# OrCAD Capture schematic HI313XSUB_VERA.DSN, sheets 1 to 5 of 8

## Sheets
1 PAGE1_Title Page
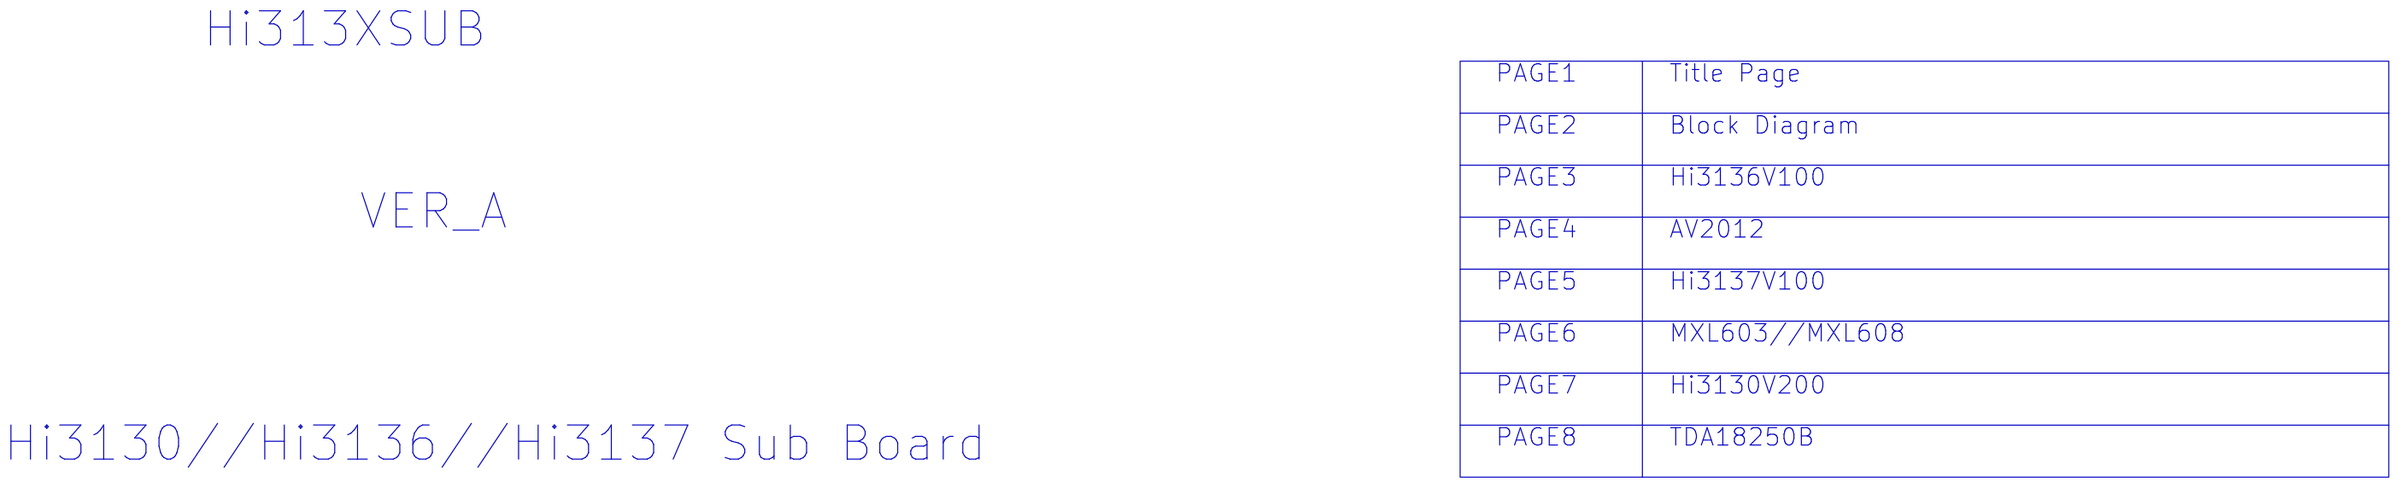
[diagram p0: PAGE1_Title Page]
2 PAGE2_Block Diagram: size Custom
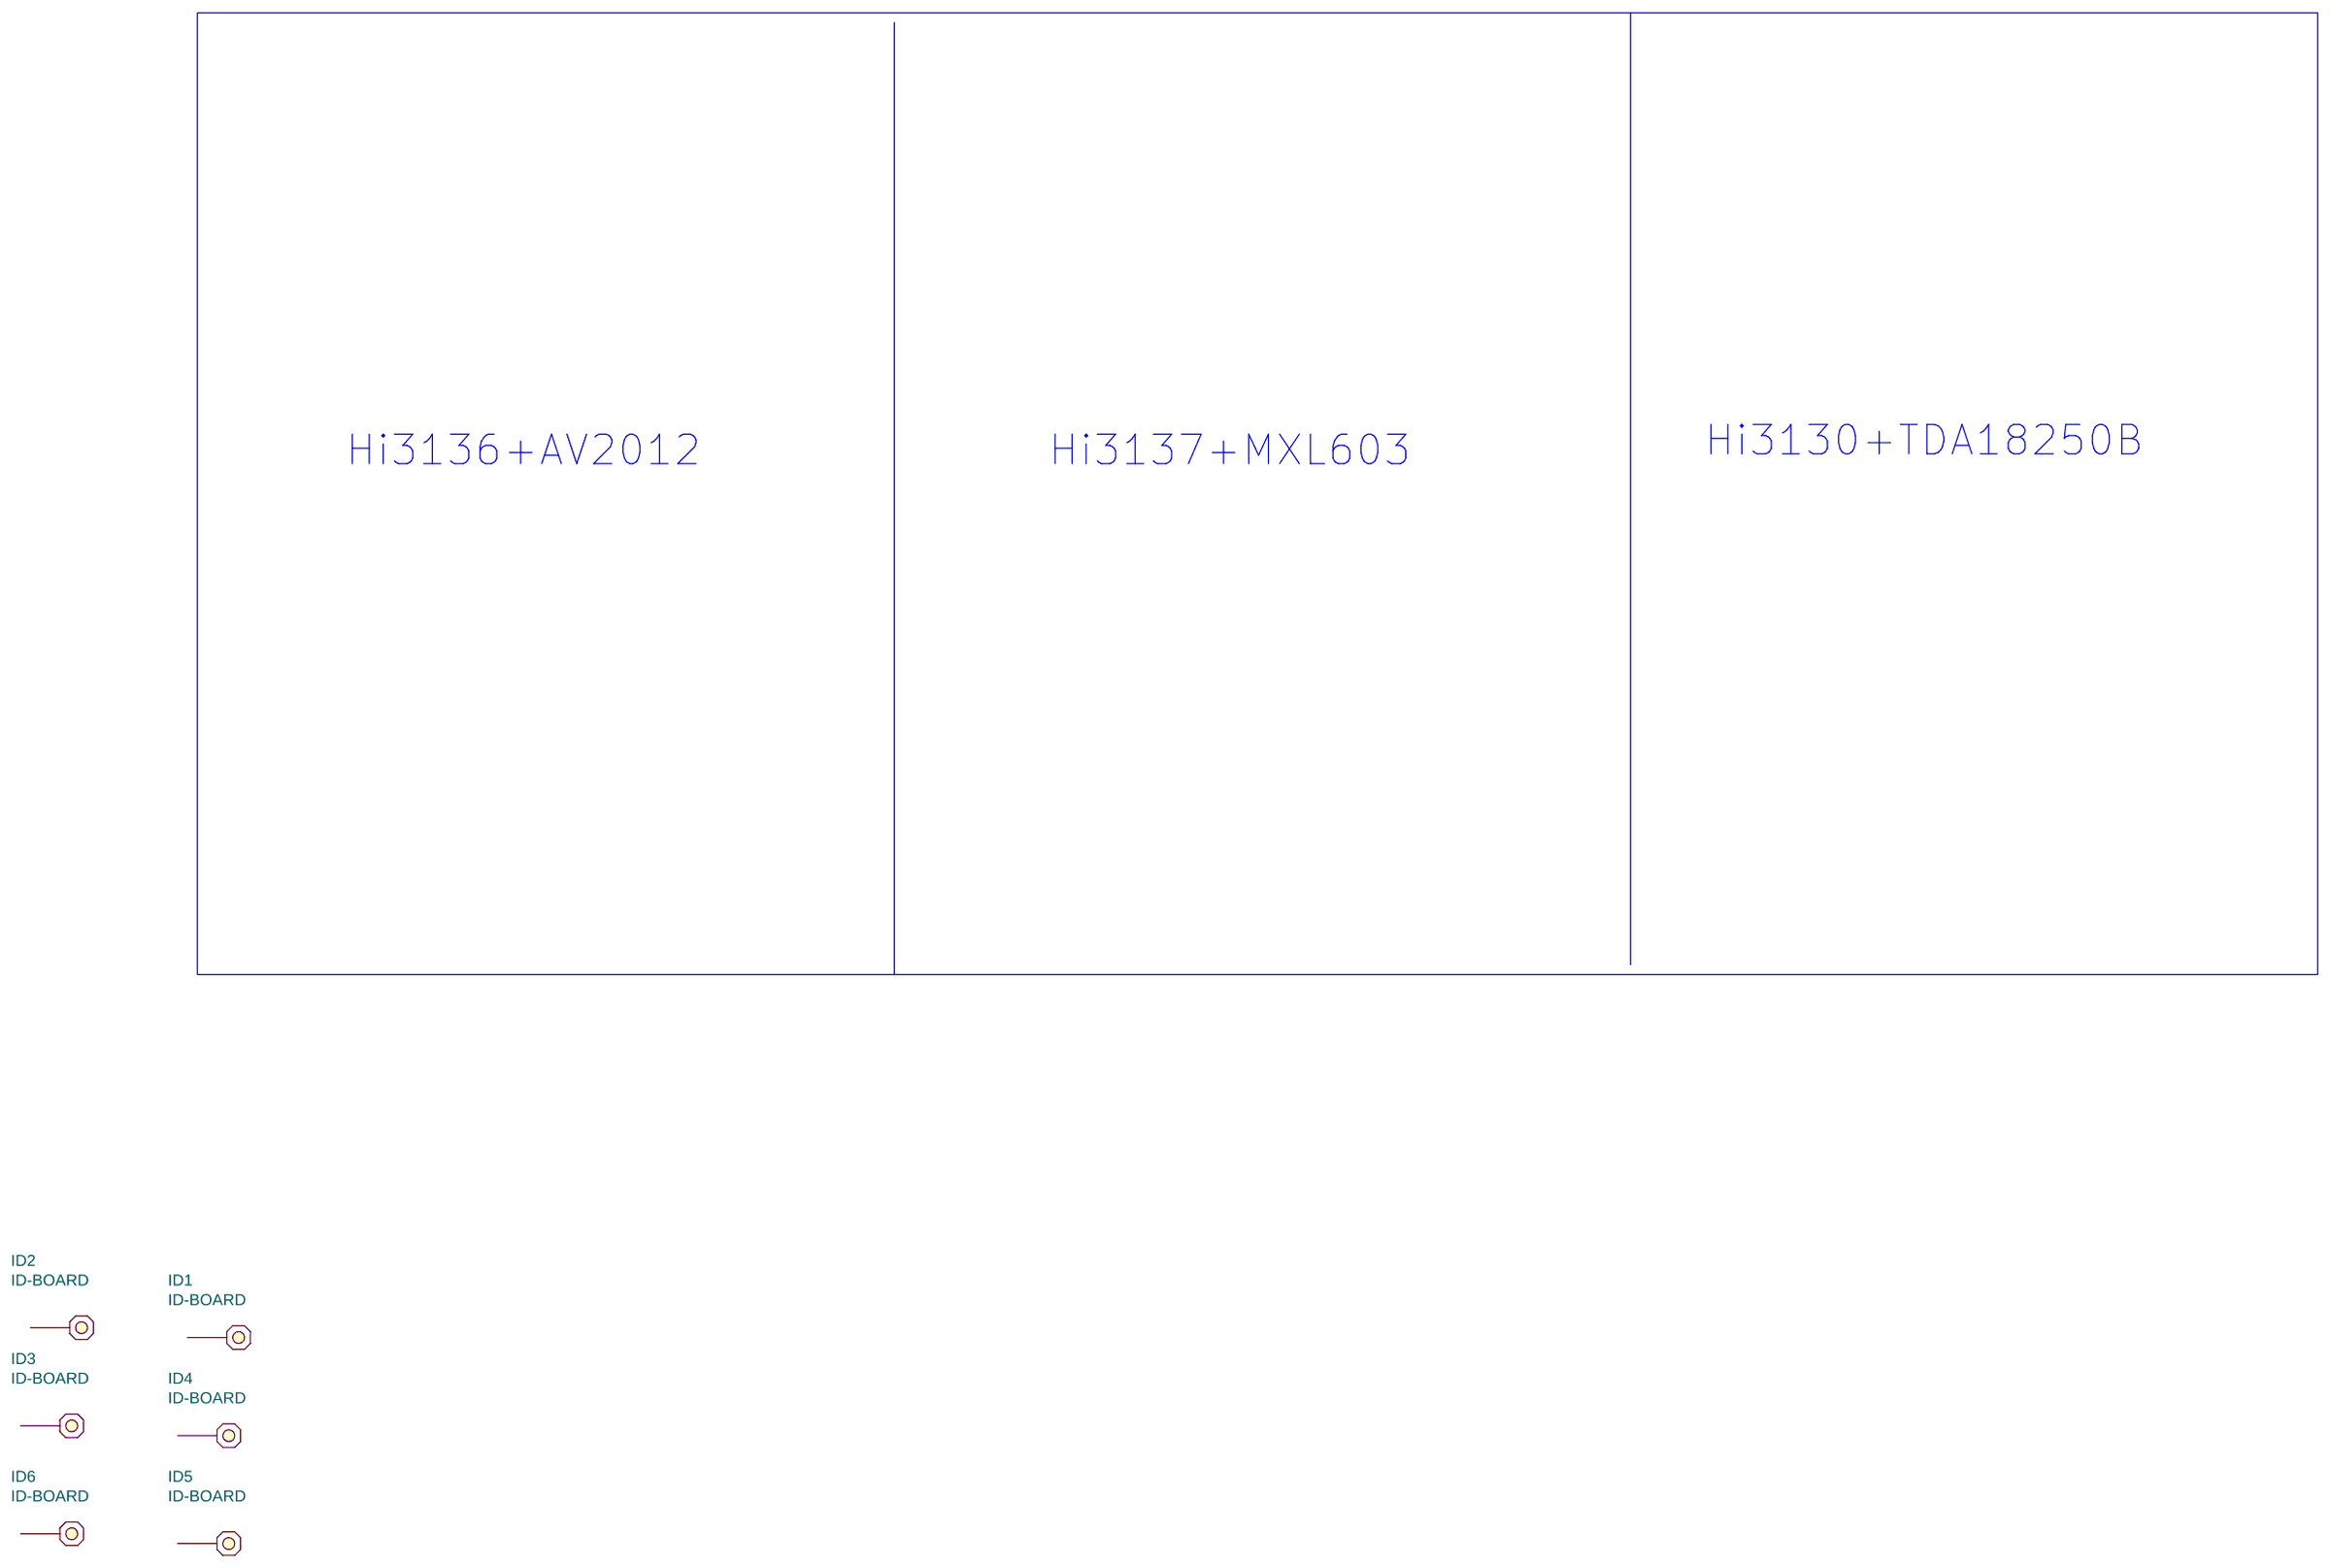
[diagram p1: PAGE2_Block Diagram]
3 PAGE3_Hi3136V100: size Custom
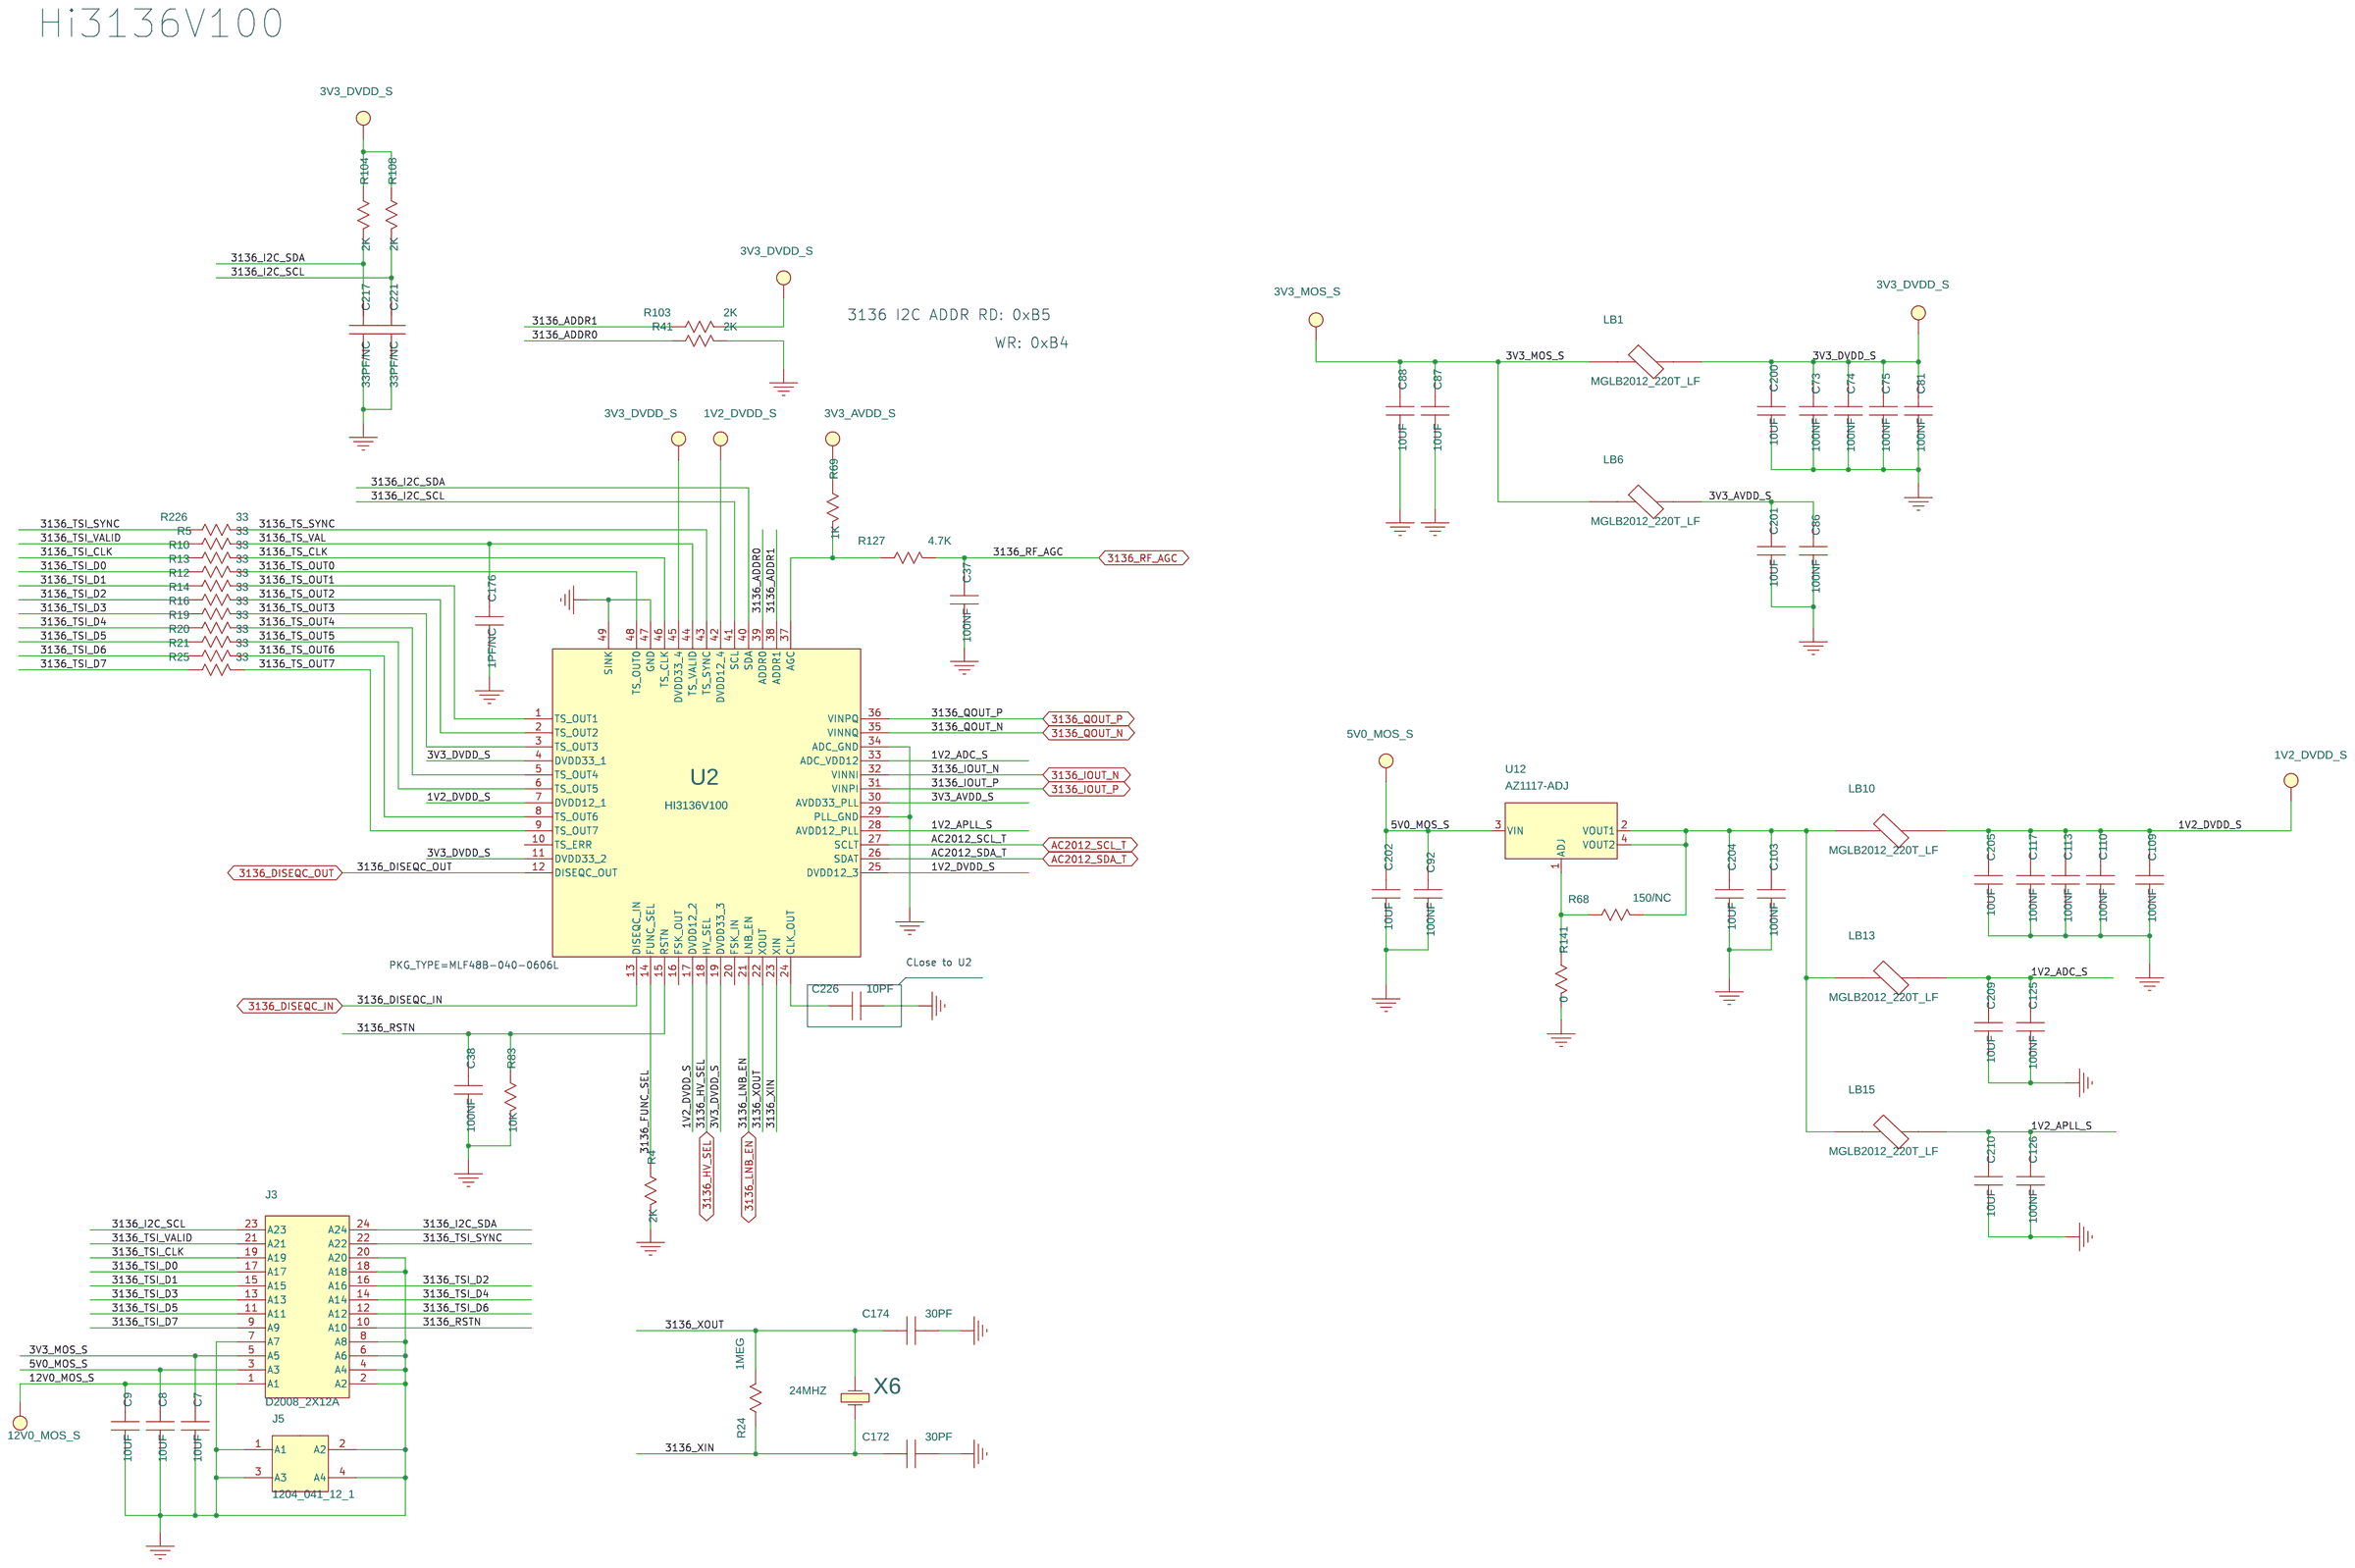
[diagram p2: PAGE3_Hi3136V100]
4 PAGE4_AV2012: size Custom
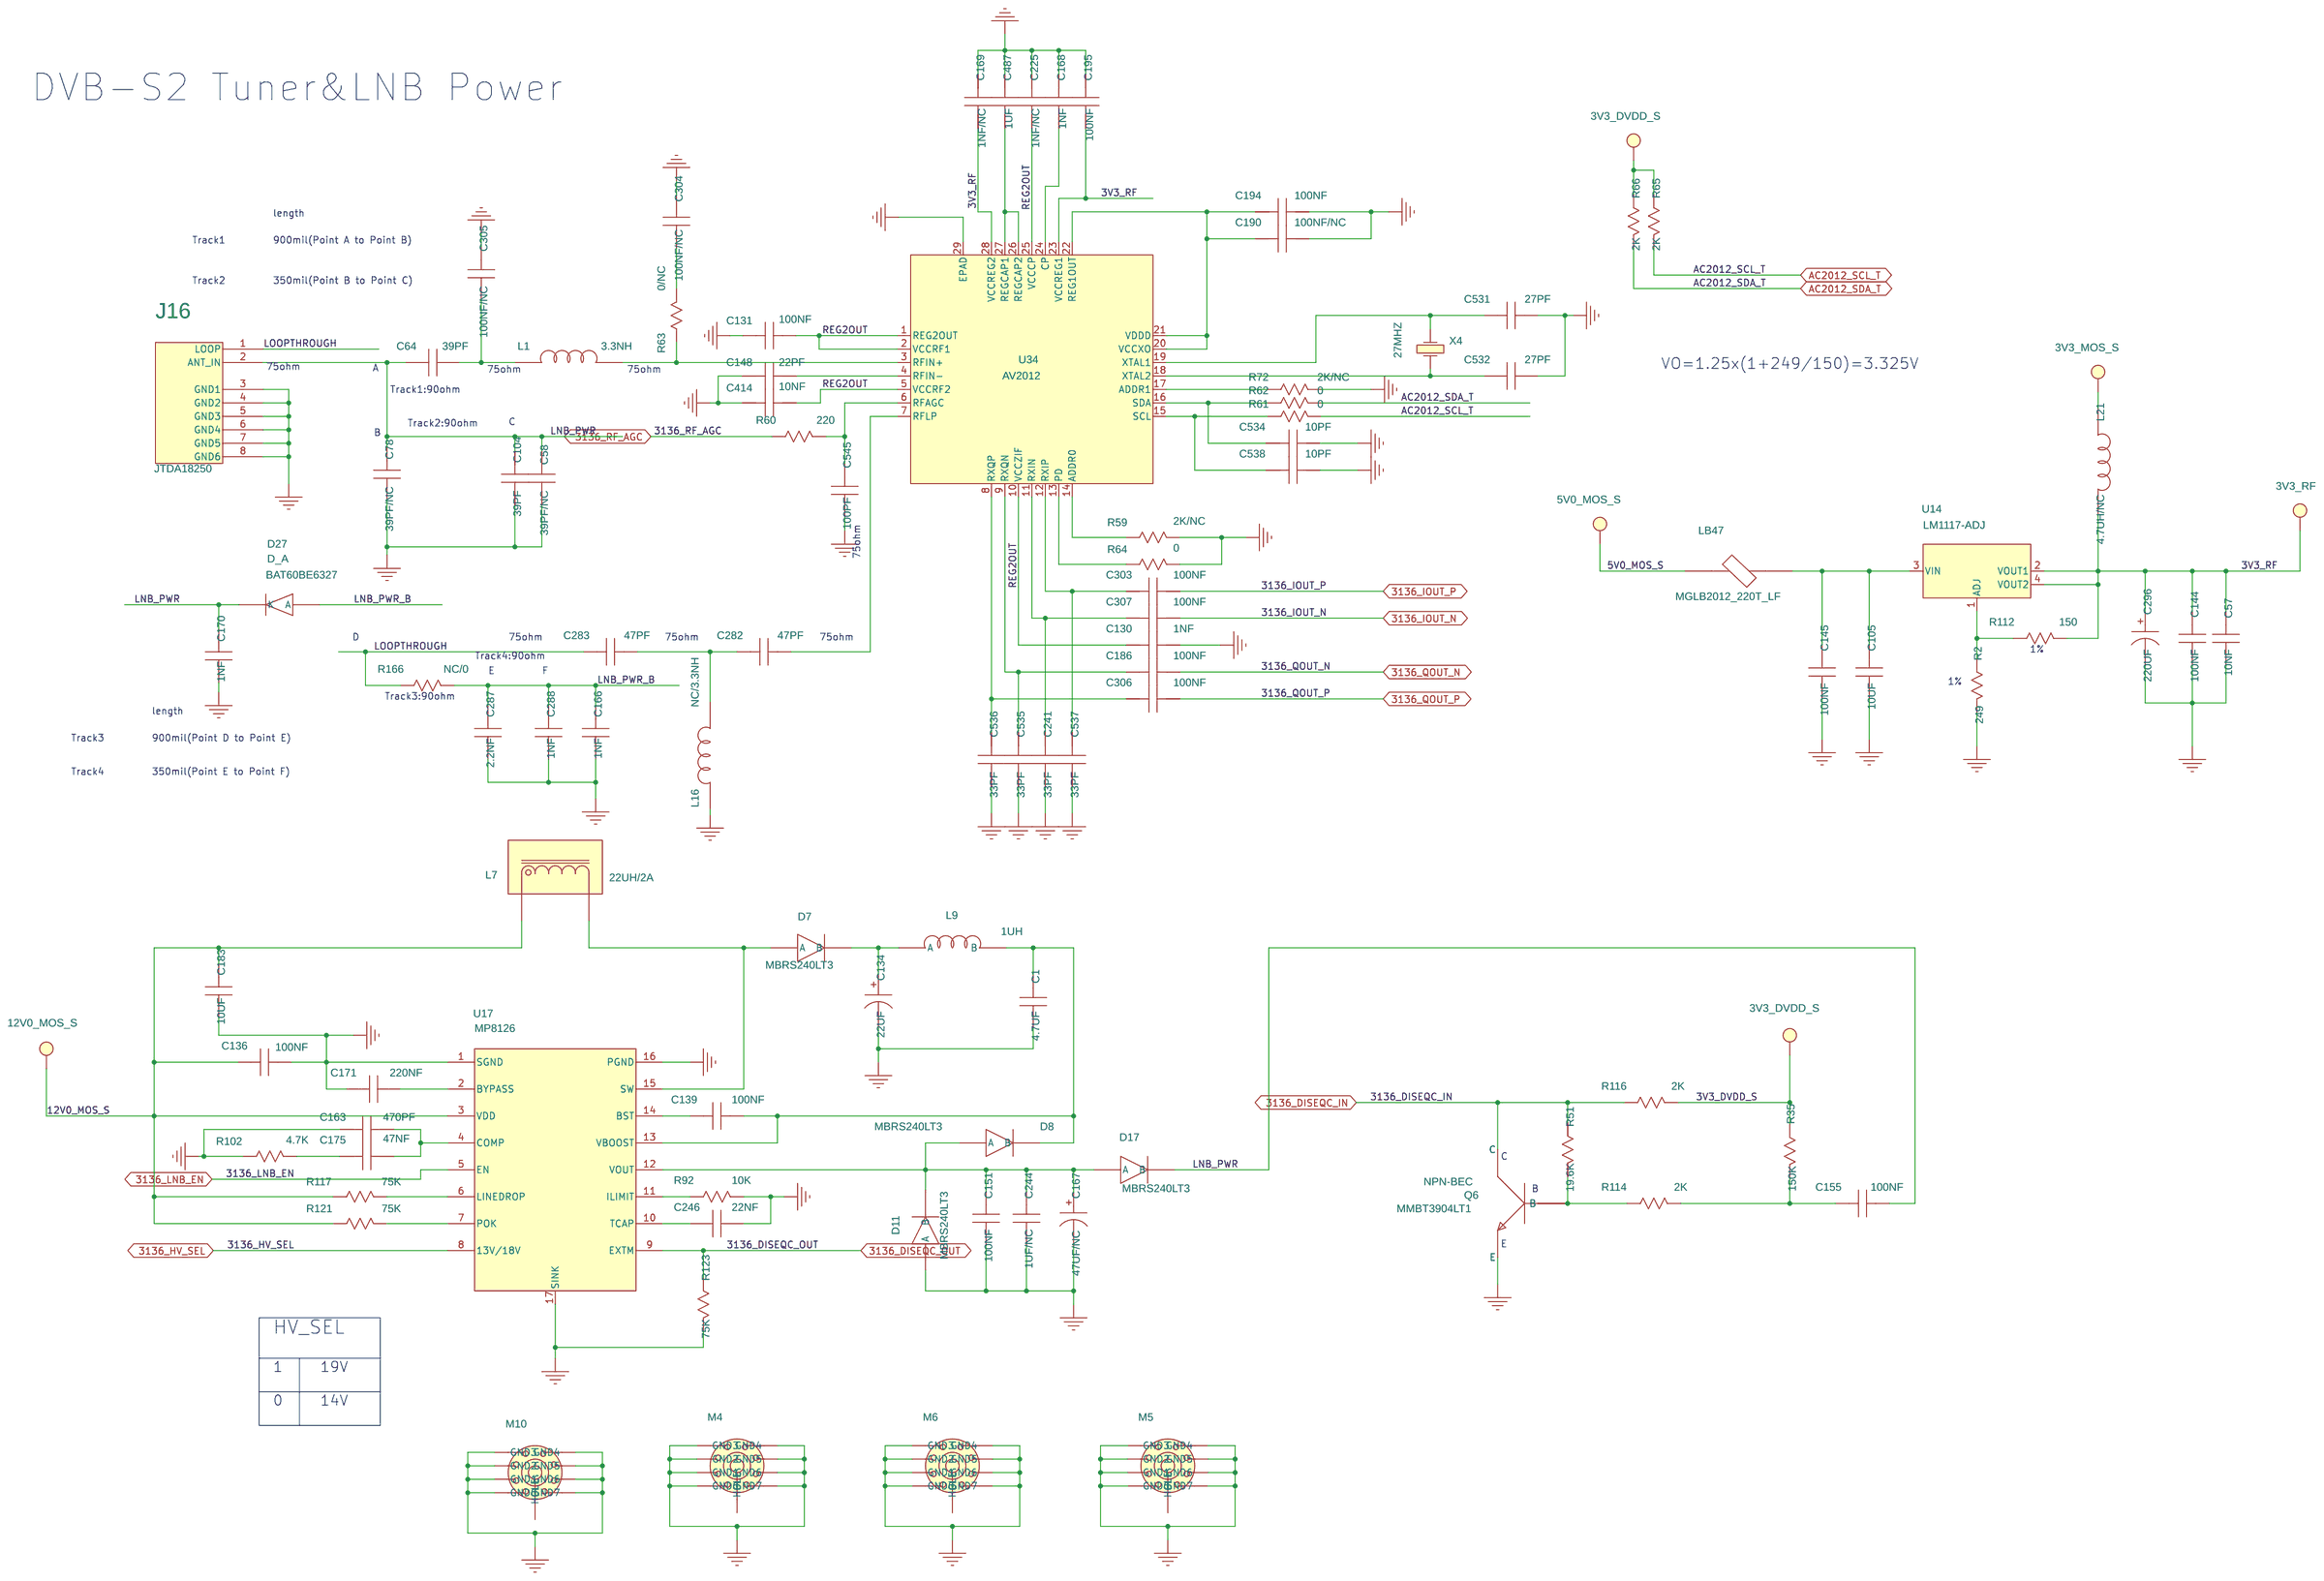
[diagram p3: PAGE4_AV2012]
5 PAGE5_Hi3137V100: size Custom
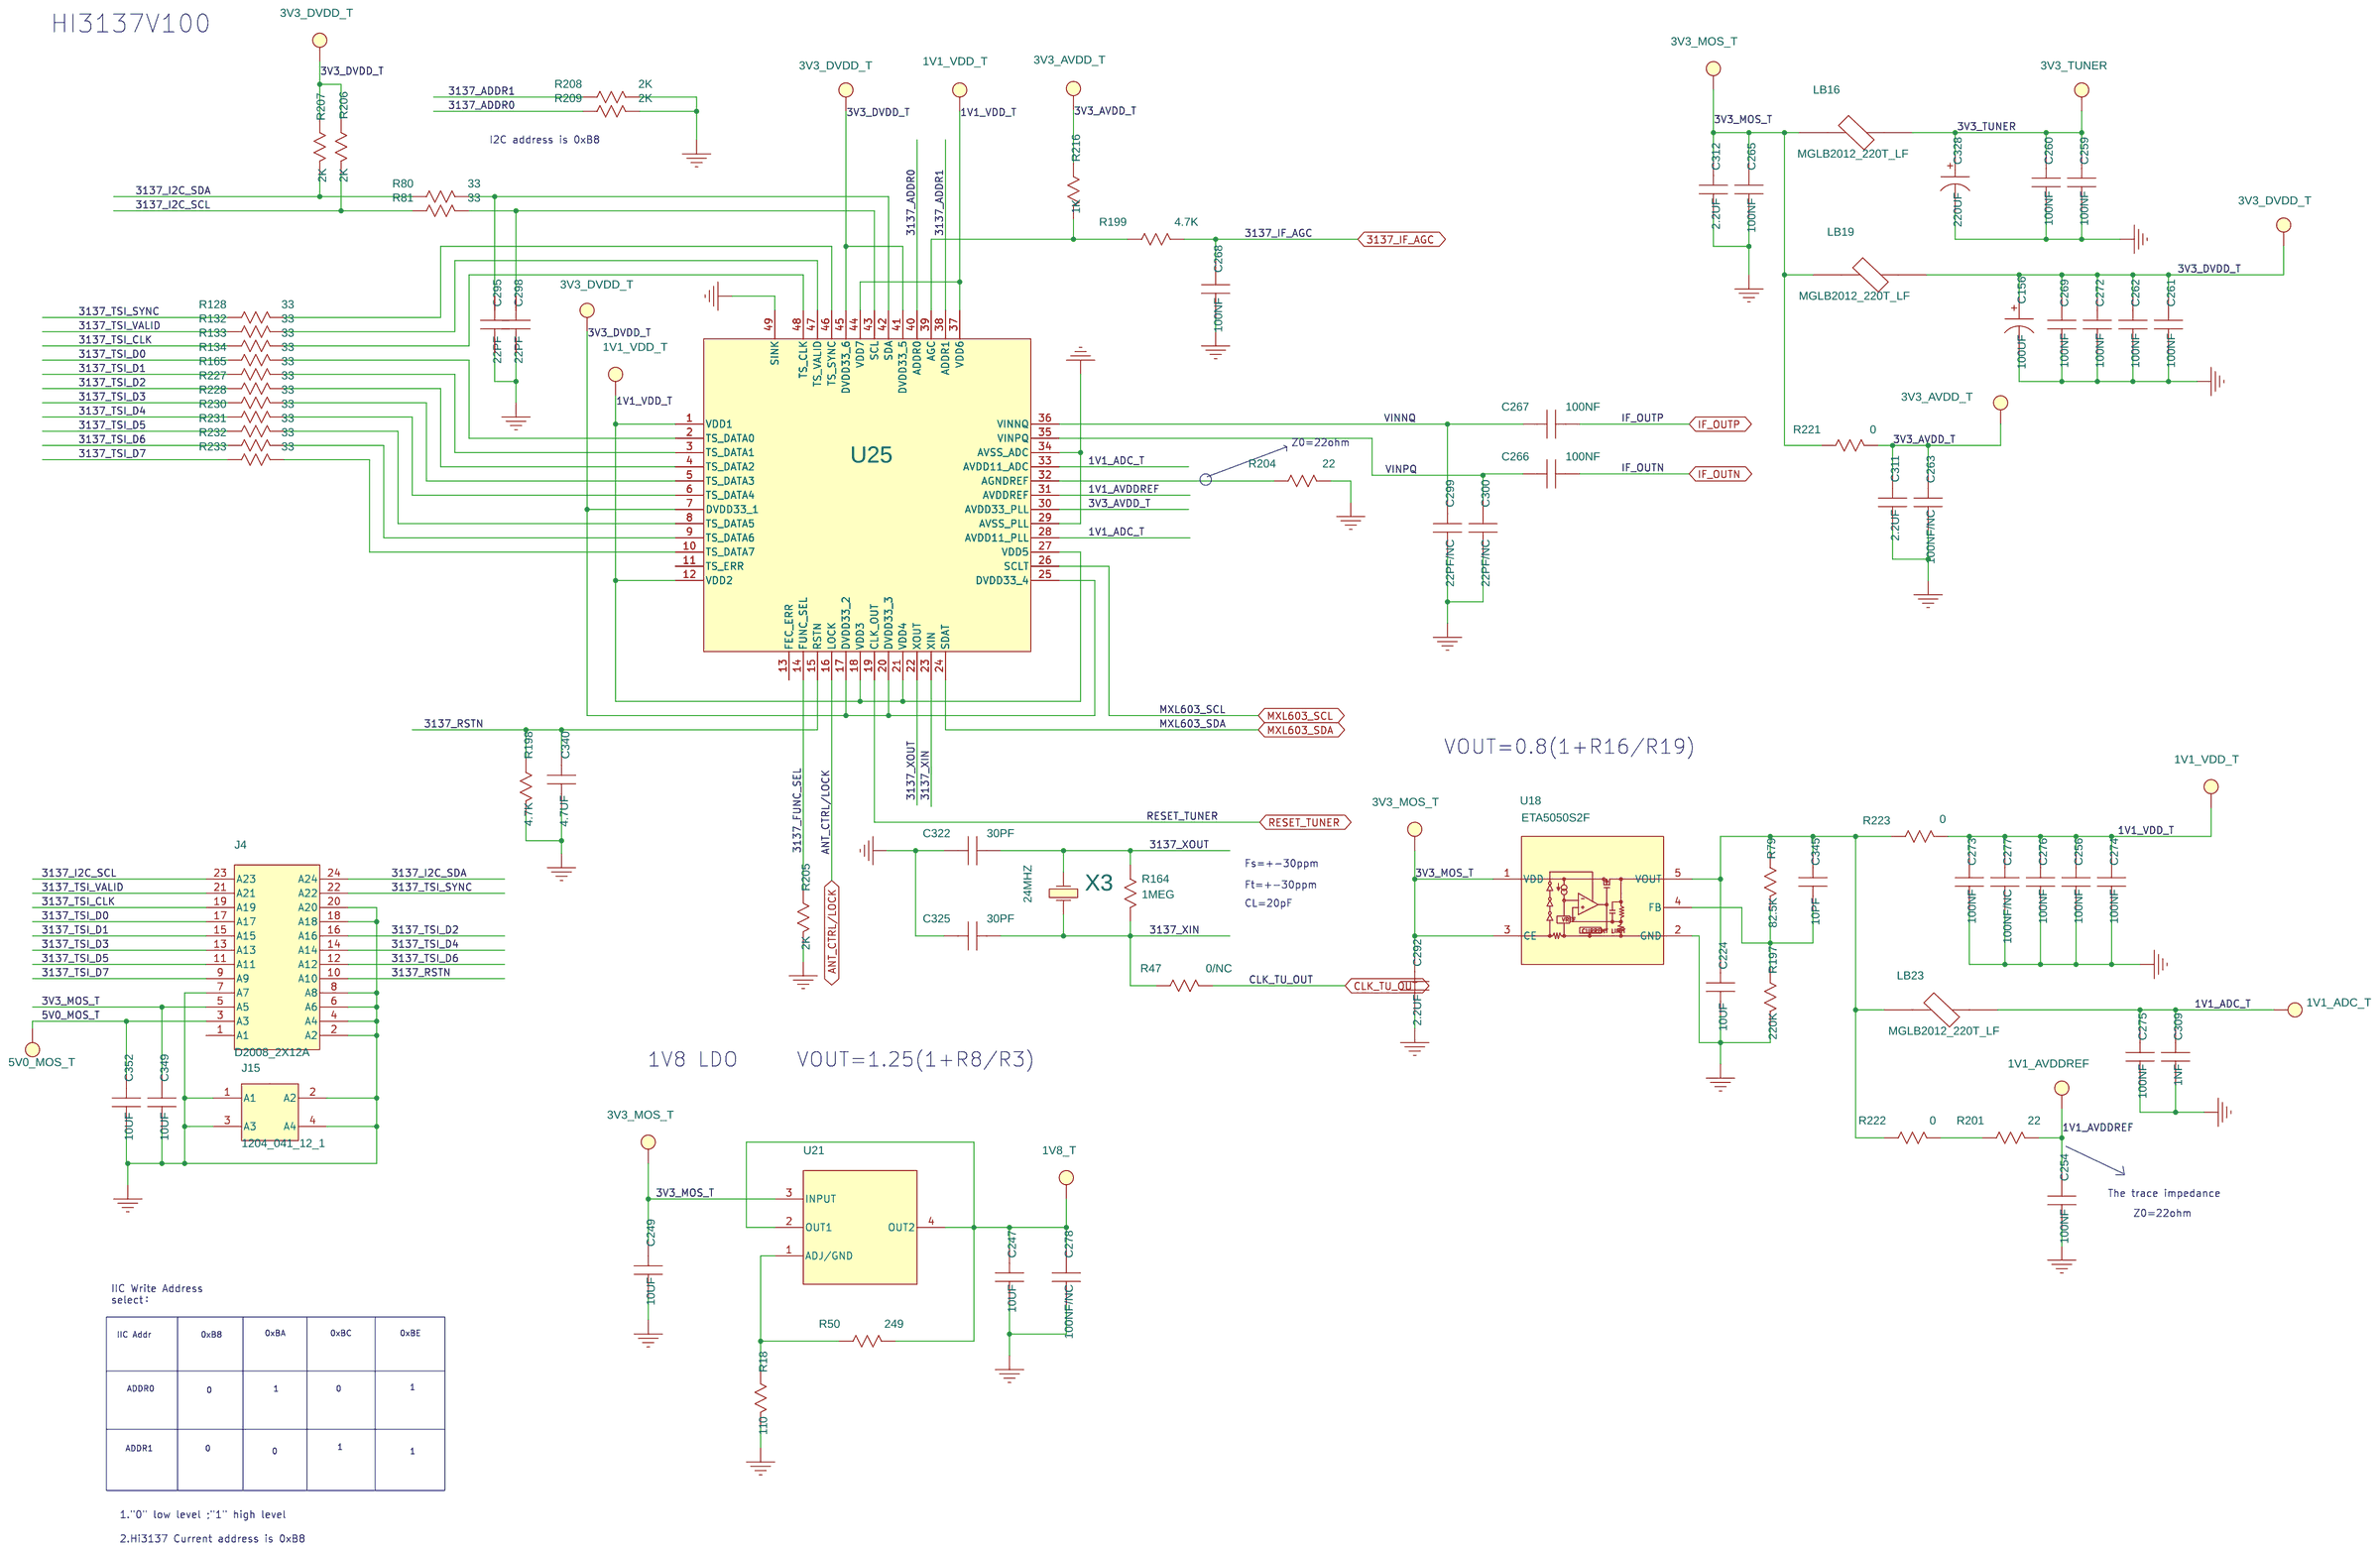
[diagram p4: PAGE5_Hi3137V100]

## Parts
sheet PAGE2_Block Diagram
ID1  ID-BOARD  [ID-BOARD]
ID2  ID-BOARD  [ID-BOARD]
ID3  ID-BOARD  [ID-BOARD]
ID4  ID-BOARD  [ID-BOARD]
ID5  ID-BOARD  [ID-BOARD]
ID6  ID-BOARD  [ID-BOARD]
sheet PAGE3_Hi3136V100
C7  10UF  [SC0603]
C8  10UF  [SC0805]
C9  10UF  [SC0805]
C37  100NF  [SC0402]
C38  100NF  [SC0402]
C73  100NF  [SC0402]
C74  100NF  [SC0402]
C75  100NF  [SC0402]
C81  100NF  [SC0402]
C86  100NF  [SC0402]
C87  10UF  [SC0603]
C88  10UF  [SC0603]
C92  100NF  [SC0402]
C103  100NF  [SC0402]
C109  100NF  [SC0402]
C110  100NF  [SC0402]
C113  100NF  [SC0402]
C117  100NF  [SC0402]
C125  100NF  [SC0402]
C126  100NF  [SC0402]
C172  30PF  [SC0402]
C174  30PF  [SC0402]
C176  1PF/NC  [SC0402]
C200  10UF  [SC0603]
C201  10UF  [SC0603]
C202  10UF  [SC0603]
C204  10UF  [SC0603]
C205  10UF  [SC0603]
C209  10UF  [SC0603]
C210  10UF  [SC0603]
C217  33PF/NC  [SC0402]
C221  33PF/NC  [SC0402]
C226  10PF  [SC0402]
J3  WBC2X12  [HEAD0212-RM-SUB]
J5  HEAD2X2  [HEAD0202-RM]
LB1  LB  [SL0805]
LB6  LB  [SL0805]
LB10  LB  [SL0805]
LB13  LB  [SL0805]
LB15  LB  [SL0805]
R4  2K  [SR0402]
R5  33  [SR0402]
R10  33  [SR0402]
R12  33  [SR0402]
R13  33  [SR0402]
R14  33  [SR0402]
R16  33  [SR0402]
R19  33  [SR0402]
R20  33  [SR0402]
R21  33  [SR0402]
R24  1MEG  [SR0402]
R25  33  [SR0402]
R41  2K  [SR0402]
R68  150/NC  [SR0402]
R69  1K  [SR0402]
R83  10K  [SR0402]
R103  2K  [SR0402]
R104  2K  [SR0402]
R108  2K  [SR0402]
R127  4.7K  [SR0402]
R141  0  [SR0603]
R226  33  [SR0402]
U2  HI3136V100  [MLF48B-040-0606L]
U12  AZ1117-ADJ  [TO-252]
X6  24MHZ  [SX2-1205]
sheet PAGE4_AV2012
C1  4.7UF  [SC1210]
C57  10NF  [HSC0402]
C58  39PF/NC  [SC0402]
C64  39PF  [SC0402]
C78  39PF/NC  [SC0402]
C104  39PF  [SC0402]
C105  10UF  [SC1206]
C130  1NF  [SC0402]
C131  100NF  [SC0402]
C134  22UF  [CAPC2-100-200]
C136  100NF  [SC0402]
C139  100NF  [SC0402]
C144  100NF  [SC0402]
C145  100NF  [SC0402]
C148  22PF  [SC0402]
C151  100NF  [SC0402]
C155  100NF  [SC0402]
C163  470PF  [SC0402]
C166  1NF  [SC0402]
C167  47UF/NC  [SCAPC2-0606]
C168  1NF  [SC0603]
C169  1NF/NC  [SC0603]
C170  1NF  [SC0402]
C171  220NF  [SC0805]
C175  47NF  [SC0402]
C183  10UF  [SC1206]
C186  100NF  [SC0402]
C190  100NF/NC  [SC0402]
C194  100NF  [SC0402]
C195  100NF  [SC0402]
C225  1NF/NC  [SC0603]
C241  33PF  [SC0402]
C244  1UF/NC  [SC1206]
C246  22NF  [SC0603]
C282  47PF  [SC0402]
C283  47PF  [SC0402]
C287  2.2NF  [SC0402]
C288  1NF  [SC0402]
C296  220UF  [CAPC2-100-250]
C303  100NF  [SC0402]
C304  100NF/NC  [SC0402]
C305  100NF/NC  [SC0402]
C306  100NF  [SC0402]
C307  100NF  [SC0402]
C414  10NF  [SC0402]
C487  1UF  [SC0603]
C531  27PF  [SC0402]
C532  27PF  [SC0402]
C534  10PF  [SC0402]
C535  33PF  [SC0402]
C536  33PF  [SC0402]
C537  33PF  [SC0402]
C538  10PF  [SC0402]
C545  100PF  [SC0402]
D7  DIODE  [SD1714A]
D8  DIODE  [SD1714A]
D11  DIODE  [SD1714A]
D17  DIODE  [SD1714A]
D27  D_A  [HSOD323A]
J16  JTDA18250  [JTDA18250]
L1  3.3NH  [SL0402]
L7  22UH/2A  [L6X6X4_5]
L9  1UH  [SWPA4020S]
L16  NC/3.3NH  [SL0402]
L21  4.7UH/NC  [HSL1007]
LB47  LB  [SL0805]
M4  HOLE-8STARS  [HOLE138-8STAR]
M5  HOLE-8STARS  [HOLE138-8STAR]
M6  HOLE-8STARS  [HOLE138-8STAR]
M10  HOLE-8STARS  [HOLE138-8STAR]
Q6  NPN-BEC  [SOT23]
R2  249  [SR0603]
R35  150K  [SR0603]
R51  19.6K  [SR0603]
R59  2K/NC  [SR0402]
R60  220  [SR0402]
R61  0  [SR0402]
R62  0  [SR0402]
R63  0/NC  [SR0402]
R64  0  [SR0402]
R65  2K  [SR0402]
R66  2K  [SR0402]
R72  2K/NC  [SR0402]
R92  10K  [SR0402]
R102  4.7K  [SR0402]
R112  150  [SR0402]
R114  2K  [SR0603]
R116  2K  [SR0603]
R117  75K  [SR0402]
R121  75K  [SR0402]
R123  75K  [SR0402]
R166  NC/0  [SR0402]
U14  LM1117-ADJ  [SOT223A]
U17  MP8126  [TSSOP16EP]
U34  AV2012  [QFN28B-040-0404LH]
X4  27MHZ  [SX2-1205]
sheet PAGE5_Hi3137V100
C156  100UF  [CAPC2-79-217]
C224  10UF  [SC0805]
C247  10UF  [SC0805]
C249  10UF  [SC0805]
C254  100NF  [SC0402]
C256  100NF  [SC0402]
C259  100NF  [SC0402]
C260  100NF  [SC0402]
C261  100NF  [SC0402]
C262  100NF  [SC0402]
C263  100NF/NC  [SC0402]
C265  100NF  [SC0402]
C266  100NF  [SC0402]
C267  100NF  [SC0402]
C268  100NF  [SC0402]
C269  100NF  [SC0402]
C272  100NF  [SC0402]
C273  100NF  [SC0402]
C274  100NF  [SC0402]
C275  100NF  [SC0402]
C276  100NF  [SC0402]
C277  100NF/NC  [SC0402]
C278  100NF/NC  [SC0402]
C292  2.2UF  [SC0603]
C295  22PF  [SC0402]
C298  22PF  [SC0402]
C299  22PF/NC  [SC0402]
C300  22PF/NC  [SC0402]
C309  1NF  [SC0402]
C311  2.2UF  [SC0805]
C312  2.2UF  [SC0805]
C322  30PF  [SC0402]
C325  30PF  [SC0402]
C328  220UF  [CAPC2-100-250]
C340  4.7UF  [SC0603]
C345  10PF  [SC0402]
C349  10UF  [SC0805]
C352  10UF  [SC0805]
J4  WBC2X12  [HEAD0212-RM-SUB]
J15  HEAD2X2  [HEAD0202-RM]
LB16  LB  [SL0805]
LB19  LB  [SL0805]
LB23  LB  [SL0805]
R18  110  [SR0603]
R47  0/NC  [SR0402]
R50  249  [SR0603]
R79  82.5K  [SR0603]
R80  33  [SR0402]
R81  33  [SR0402]
R128  33  [SR0402]
R132  33  [SR0402]
R133  33  [SR0402]
R134  33  [SR0402]
R164  1MEG  [SR0402]
R165  33  [SR0402]
R197  220K  [SR0603]
R198  4.7K  [SR0603]
R199  4.7K  [SR0603]
R201  22  [SR0402]
R204  22  [SR0402]
R205  2K  [SR0402]
R206  2K  [SR0402]
R207  2K  [SR0402]
R208  2K  [SR0402]
R209  2K  [SR0402]
R216  1K  [SR0603]
R221  0  [SR0603]
R222  0  [SR0603]
R223  0  [SR0603]
R227  33  [SR0402]
R228  33  [SR0402]
R230  33  [SR0402]
R231  33  [SR0402]
R232  33  [SR0402]
R233  33  [SR0402]
U18  ETA5050  [SOT23-5]
U21  TLV1117CKTPR  [SOT223A]
U25  HI3137V100  [MLF48G-040-0606L]
X3  24MHZ  [SX2-1205]

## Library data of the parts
ID1-ID6 = ID-BOARD
C7 C87 C88 C200-C202 C204 C205 C209 C210 = C: %182%%238%%182%%168%%185%%164%%215%%247%%181%%231%%209%%185%(V): 6.3; %195%%232%%202%%246%: SMD陶瓷电容-6.3V-10000NF-+/-20%-X5R-0603-BT,TS16949; %208%%161%%192%%224%%195%%251%%179%%198%: SMD陶瓷电容; CODE: 8070649; COMPONENT_HIGH_MAX: 0.9MM; DEVICE: C1608X5R0J106MT0A0E
C8 C9 C349 C352 = C: %182%%238%%182%%168%%185%%164%%215%%247%%181%%231%%209%%185%(V): 25; %195%%232%%202%%246%: SMD陶瓷电容-25V-10000NF-+/-20%-X5R-0805; %208%%161%%192%%224%%195%%251%%179%%198%: SMD陶瓷电容; CODE: 8071629; COMPONENT_HIGH_MAX: 1.45MM; DEVICE: C2012X5R1E106KT000N1
C37 C38 C136 C139 C144 C145 C151 C155 C265 = C: %182%%238%%182%%168%%185%%164%%215%%247%%181%%231%%209%%185%(V): 16; %195%%232%%202%%246%: SMD陶瓷电容-16V-100NF-+/-10%-X7R-0402-BT; %208%%161%%192%%224%%195%%251%%179%%198%: SMD陶瓷电容; CODE: 8070614; COMPONENT_HIGH_MAX: 0.6MM; DEVICE: RMEMK105BJ104KV_FR
C73-C75 C81 C86 C92 C103 C109 C110 C113 C117 C125 C126 = C: %182%%238%%182%%168%%185%%164%%215%%247%%181%%231%%209%%185%(V): 10; %195%%232%%202%%246%: SMD陶瓷电容-10V-100NF-+/-10%-X5R-0402; %208%%161%%192%%224%%195%%251%%179%%198%: SMD陶瓷电容; CODE: 8070561; COMPONENT_HIGH_MAX: 0.55MM; DEVICE: C0402C104K8PAC_7867
C172 C174 C322 C325 = C: %182%%238%%182%%168%%185%%164%%215%%247%%181%%231%%209%%185%(V): 50; %195%%232%%202%%246%: SMD陶瓷电容-50V-0.03NF-+/-5%-NPO-0402; %208%%161%%192%%224%%195%%251%%179%%198%: SMD陶瓷电容; CODE: 8070604; COMPONENT_HIGH_MAX: 0.55MM; DEVICE: GRM1555C1H300J
C176 = C: %182%%238%%182%%168%%185%%164%%215%%247%%181%%231%%209%%185%(V): 50; %195%%232%%202%%246%: SMD陶瓷电容-50V-0.001NF-+/-0.1PF-NPO-0402-BT; %208%%161%%192%%224%%195%%251%%179%%198%: SMD陶瓷电容; CODE: 8070578; COMPONENT_HIGH_MAX: 0.55MM; DEVICE: GRM1555C1H1R0B
C217 C221 C241 C535-C537 = C: %182%%238%%182%%168%%185%%164%%215%%247%%181%%231%%209%%185%(V): 50; %195%%232%%202%%246%: SMD陶瓷电容-50V-0.033NF-+/-5%-NP0-0402-BT; %208%%161%%192%%224%%195%%251%%179%%198%: SMD陶瓷电容; CODE: 8070547; COMPONENT_HIGH_MAX: 0.55MM; DEVICE: CC0402JRNPO9BN330
C226 C345 = C: %182%%238%%182%%168%%185%%164%%215%%247%%181%%231%%209%%185%(V): 50; %195%%232%%202%%246%: SMD陶瓷电容-50V-0.01NF-+/-5%-NP0-0402-BT; %208%%161%%192%%224%%195%%251%%179%%198%: SMD陶瓷电容; CODE: 8070530; COMPONENT_HIGH_MAX: 0.56MM; DEVICE: 04025A100JAT2A
J3 J4 = WBC2X12: %195%%232%%202%%246%: 华为文档 00383947 - 得康（D2008－2×12A） A; CODE: 383947; COMPONENT_HIGH_MAX: 6.7MM; DEVICE: D2008_2X12A
J5 J15 = HEAD2X2: %195%%232%%202%%246%: 插针-普通方脚插针-4PIN-双排-弯脚-5.84MM-3.18MM-2.54MM-THT; %208%%161%%192%%224%%195%%251%%179%%198%: 插针; CODE: 14050061; COMPONENT_HIGH_MAX: 5.2MM; DEVICE: 1204_041_12_1
LB1 LB6 LB10 LB13 LB15 LB23 = LB: %195%%232%%202%%246%: EMI磁珠-+/-25%-220OHM-0.05OHM-2A-0805; %208%%161%%192%%224%%195%%251%%179%%198%: EMI磁珠; CODE: 10070012; COMPONENT_HIGH_MAX: 1.05MM; DEVICE: MGLB2012_220T_LF
R4 R41 R59 R72 R103 R104 R108 R205-R209 = R: %182%%238%%182%%168%%185%%166%%194%%202%(W): 0.06; %195%%232%%202%%246%: 片式厚膜电阻器-0.0625W-2000OHM-+/-1%-0402-BT; %208%%161%%192%%224%%195%%251%%179%%198%: 片式厚膜电阻器; %215%%232%%214%%181%%212%%202%%208%%237%%198%%171%%178%%238%: +/-1%; CODE: 7091354; COMPONENT_HIGH_MAX: 0.4MM; DEVICE: RC_02W2001FT
R5 R10 R12-R14 R16 R19-R21 R25 R80 R81 R128 R132-R134 R165 R226-R228 R230-R233 = R: %182%%238%%182%%168%%185%%166%%194%%202%(W): 0.06; %195%%232%%202%%246%: 片式厚膜电阻器-0.0625W-33OHM-+/-1%-0402; %208%%161%%192%%224%%195%%251%%179%%198%: 片式厚膜电阻器; %215%%232%%214%%181%%212%%202%%208%%237%%198%%171%%178%%238%: +/-1%; CODE: 7090836; COMPONENT_HIGH_MAX: 0.4MM; DEVICE: RC0402FR_0733RL
R24 R164 = R: %182%%238%%182%%168%%185%%166%%194%%202%(W): 0.06; %195%%232%%202%%246%: 片式厚膜电阻器-0.0625W-1000000OHM-+/-1%-0402; %208%%161%%192%%224%%195%%251%%179%%198%: 片式厚膜电阻器; %215%%232%%214%%181%%212%%202%%208%%237%%198%%171%%178%%238%: +/-1%; CODE: 7090857; COMPONENT_HIGH_MAX: 0.4MM; DEVICE: RK73H1ETTP1004F
R68 = R: %182%%238%%182%%168%%185%%166%%194%%202%(W): 0.06; %195%%232%%202%%246%: 片式厚膜电阻器-0.0625W-150OHM-+/-5%-0402; %208%%161%%192%%224%%195%%251%%179%%198%: 片式厚膜电阻器; %215%%232%%214%%181%%212%%202%%208%%237%%198%%171%%178%%238%: +/-5%; CODE: 7090788; COMPONENT_HIGH_MAX: 0.4MM; DEVICE: RK73B1ELTP151J
R69 = R: %182%%238%%182%%168%%185%%166%%194%%202%(W): 0.06; %195%%232%%202%%246%: 片式厚膜电阻器-0.0625W-1000OHM-+/-5%-0402-BT; %208%%161%%192%%224%%195%%251%%179%%198%: 片式厚膜电阻器; %215%%232%%214%%181%%212%%202%%208%%237%%198%%171%%178%%238%: +/-5%; CODE: 7090809; COMPONENT_HIGH_MAX: 0.4MM; DEVICE: RC0402JR_071KL
R83 = R: %182%%238%%182%%168%%185%%166%%194%%202%(W): 0.06; %195%%232%%202%%246%: 片式厚膜电阻器-0.0625W-10000OHM-+/-5%-0402-BT; %208%%161%%192%%224%%195%%251%%179%%198%: 片式厚膜电阻器; %215%%232%%214%%181%%212%%202%%208%%237%%198%%171%%178%%238%: +/-5%; CODE: 7090815; COMPONENT_HIGH_MAX: 0.4MM; DEVICE: RC_02W103JT
R102 R127 = R: %182%%238%%182%%168%%185%%166%%194%%202%(W): 0.06; %195%%232%%202%%246%: 片式厚膜电阻器-0.0625W-4700OHM-+/-5%-0402-BT; %208%%161%%192%%224%%195%%251%%179%%198%: 片式厚膜电阻器; %215%%232%%214%%181%%212%%202%%208%%237%%198%%171%%178%%238%: +/-5%; CODE: 7090793; COMPONENT_HIGH_MAX: 0.4MM; DEVICE: RK73B1ELTP472J
R141 R221-R223 = R: %182%%238%%182%%168%%185%%166%%194%%202%(W): 0.1; %195%%232%%202%%246%: 片式厚膜电阻器-0.1W-0OHM-<50MOHM-0603-1A-BT,TS16949; %208%%161%%192%%224%%195%%251%%179%%198%: 片式厚膜电阻器; %215%%232%%214%%181%%212%%202%%208%%237%%198%%171%%178%%238%: <50MOHM; CODE: 7090522; COMPONENT_HIGH_MAX: 0.6MM; DEVICE: RC0603JR_070RL
U2 = HI3136V100
U12 = AZ1117-ADJ_0
X3 X6 = X3: %195%%232%%202%%246%: 晶体谐振器-24MHZ-20PF-+/-30PPM-40OHM-HC-49S; %208%%161%%192%%224%%195%%251%%179%%198%: 晶体谐振器; CODE: 12020090; COMPONENT_HIGH_MAX: 4.2MM; DEVICE: ESB240000F20D33
C1 = C: %182%%238%%182%%168%%185%%164%%215%%247%%181%%231%%209%%185%(V): 50; %195%%232%%202%%246%: SMD陶瓷电容-50V-4700NF-+/-20%-X7R-1210; %208%%161%%192%%224%%195%%251%%179%%198%: SMD陶瓷电容; CODE: 8070690; COMPONENT_HIGH_MAX: 2.8MM; DEVICE: C3225X7R1H475MT000E
C57 = C: %182%%238%%182%%168%%185%%164%%215%%247%%181%%231%%209%%185%(V): 50; %195%%232%%202%%246%: SMD陶瓷电容-50V-10NF-10%-X7R-0402-终端专用; %208%%161%%192%%224%%195%%251%%179%%198%: SMD陶瓷电容; CODE: 8070970; COMPONENT_HIGH_MAX: 0.55MM; DEVICE: 0402B103K500CT
C58 C64 C78 C104 = C: %182%%238%%182%%168%%185%%164%%215%%247%%181%%231%%209%%185%(V): 50; %195%%232%%202%%246%: SMD陶瓷电容-50V-0.039NF-+/-5%-NPO-0402; %208%%161%%192%%224%%195%%251%%179%%198%: SMD陶瓷电容; CODE: 8070605; COMPONENT_HIGH_MAX: 0.55MM; DEVICE: GRM1555C1H390JZ01D
C105 = C: %182%%238%%182%%168%%185%%164%%215%%247%%181%%231%%209%%185%(V): 10; %195%%232%%202%%246%: SMD陶瓷电容-10V-10000NF-+/-10% -X7R-1206; %208%%161%%192%%224%%195%%251%%179%%198%: SMD陶瓷电容; CODE: 8070729; COMPONENT_HIGH_MAX: 1.8MM; DEVICE: 1206B106K100CT
C130 C309 = C: %182%%238%%182%%168%%185%%164%%215%%247%%181%%231%%209%%185%(V): 50; %195%%232%%202%%246%: SMD陶瓷电容-50V-1NF-+/-10%-X7R-0402-BT; %208%%161%%192%%224%%195%%251%%179%%198%: SMD陶瓷电容; CODE: 8070531; COMPONENT_HIGH_MAX: 0.56MM; DEVICE: 04025C102KAT2A
C131 C186 C190 C194 C195 C303-C307 = C: %182%%238%%182%%168%%185%%164%%215%%247%%181%%231%%209%%185%(V): 10; %195%%232%%202%%246%: SMD陶瓷电容-10V-100NF-+/-10%-X5R-0402; %208%%161%%192%%224%%195%%251%%179%%198%: SMD陶瓷电容; CODE: 8070561; DEVICE: C0402C104K8PAC_7867
C134 = CP_0: %182%%238%%182%%168%%185%%164%%215%%247%%181%%231%%209%%185%(V): 50; %195%%232%%202%%246%: 非固体插装铝电容-50V-22UF-+/-20%-5*11-2-0.5MM-极性-105DEGC-1000H; %208%%161%%192%%224%%195%%251%%179%%198%: 非固体插装铝电容; CODE: 8010229; COMPONENT_HIGH_MAX: 12.5MM; DEVICE: EKMG500ETD220ME11D
C148 C295 C298-C300 = C: %182%%238%%182%%168%%185%%164%%215%%247%%181%%231%%209%%185%(V): 50; %195%%232%%202%%246%: SMD陶瓷电容-50V-0.022NF-+/-5%-NP0-0402-BT; %208%%161%%192%%224%%195%%251%%179%%198%: SMD陶瓷电容; CODE: 8070545; COMPONENT_HIGH_MAX: 0.55MM; DEVICE: RMUMK105CG220JV_F
C163 = C: %182%%238%%182%%168%%185%%164%%215%%247%%181%%231%%209%%185%(V): 50; %195%%232%%202%%246%: SMD陶瓷电容-50V-0.47NF-+/-5%-NPO-0402; %208%%161%%192%%224%%195%%251%%179%%198%: SMD陶瓷电容; CODE: 8070582; COMPONENT_HIGH_MAX: 0.55MM; DEVICE: GRM1555C1H471JA01D
C166 C170 C288 = C: %182%%238%%182%%168%%185%%164%%215%%247%%181%%231%%209%%185%(V): 50; %195%%232%%202%%246%: SMD陶瓷电容-50V-1NF-+/-10%-X7R-0402-BT; %208%%161%%192%%224%%195%%251%%179%%198%: SMD陶瓷电容; CODE: 8070531; COMPONENT_HIGH_MAX: 0.55MM; DEVICE: 04025C102KAT2A
C167 = CP_0: %182%%238%%182%%168%%185%%164%%215%%247%%181%%231%%209%%185%(V): 50; %195%%232%%202%%246%: 非固体SMD铝电容-50V-47UF-+/-20%-6.3*7.7-6.6*6.6MM-极性-105DEGC-1000H-圆柱体-温度敏感器件-工艺耐温250DEGC,5S; %208%%161%%192%%224%%195%%251%%179%%198%: 非固体SMD铝电容; CODE: 8120005; COMPONENT_HIGH_MAX: 8MM; DEVICE: MVE50VC470MF80TPE0_63X77
C168 C169 C225 = C: %182%%238%%182%%168%%185%%164%%215%%247%%181%%231%%209%%185%(V): 50; %195%%232%%202%%246%: SMD陶瓷电容-50V-1NF-+/-10%-X7R-0603; %208%%161%%192%%224%%195%%251%%179%%198%: SMD陶瓷电容; CODE: 8070249; DEVICE: 06035C102KAT2A
C171 = C: %182%%238%%182%%168%%185%%164%%215%%247%%181%%231%%209%%185%(V): 25; %195%%232%%202%%246%: SMD陶瓷电容-25V-220NF-+/-10%-X7R-0805; %208%%161%%192%%224%%195%%251%%179%%198%: SMD陶瓷电容; CODE: 8070567; COMPONENT_HIGH_MAX: 1.45MM; DEVICE: C0805C224K3RAC_7800
C175 = C: %182%%238%%182%%168%%185%%164%%215%%247%%181%%231%%209%%185%(V): 25; %195%%232%%202%%246%: SMD陶瓷电容-25V-47NF-+/-10%-X7R-0402-所有; %208%%161%%192%%224%%195%%251%%179%%198%: SMD陶瓷电容; CODE: 8070855; COMPONENT_HIGH_MAX: 0.55MM; DEVICE: C0402C473K3RAC7867
C183 = C: %182%%238%%182%%168%%185%%164%%215%%247%%181%%231%%209%%185%(V): 25; %195%%232%%202%%246%: SMD陶瓷电容-25V-10000NF-+/-20%-X7R-1206-所有; %208%%161%%192%%224%%195%%251%%179%%198%: SMD陶瓷电容; CODE: 8070865; COMPONENT_HIGH_MAX: 1.8MM; DEVICE: CETMK316B7106ML_T
C244 = C: %182%%238%%182%%168%%185%%164%%215%%247%%181%%231%%209%%185%(V): 50; %195%%232%%202%%246%: SMD陶瓷电容-50V-1000NF-+/-10%-X7R-1206; %208%%161%%192%%224%%195%%251%%179%%198%: SMD陶瓷电容; CODE: 8070728; COMPONENT_HIGH_MAX: 1.9MM; DEVICE: 12065C105KAT2A
C246 = C: %182%%238%%182%%168%%185%%164%%215%%247%%181%%231%%209%%185%(V): 25; %195%%232%%202%%246%: SMD陶瓷电容-25V-22NF-+/-10%-X7R-0603; %208%%161%%192%%224%%195%%251%%179%%198%: SMD陶瓷电容; CODE: 8070246; COMPONENT_HIGH_MAX: 0.9MM; DEVICE: CC0603KRX7R8BB223
C282 C283 = C: %182%%238%%182%%168%%185%%164%%215%%247%%181%%231%%209%%185%(V): 50; %195%%232%%202%%246%: SMD陶瓷电容-50V-0.047NF-+/-5%-NP0-0402; %208%%161%%192%%224%%195%%251%%179%%198%: SMD陶瓷电容; CODE: 8070549; COMPONENT_HIGH_MAX: 0.55MM; DEVICE: C0402C470J5GAC_7867
C287 = C: %182%%238%%182%%168%%185%%164%%215%%247%%181%%231%%209%%185%(V): 50; %195%%232%%202%%246%: SMD陶瓷电容-50V-2.2NF-+/-10%-X7R-0402; %208%%161%%192%%224%%195%%251%%179%%198%: SMD陶瓷电容; CODE: 8070557; COMPONENT_HIGH_MAX: 0.56MM; DEVICE: CM05X7R222K50AH
C296 = CP_0: %182%%238%%182%%168%%185%%164%%215%%247%%181%%231%%209%%185%(V): 16; %195%%232%%202%%246%: 非固体插装铝电容-16V-220UF-±20%-6.3*11-2.5-0.5MM-极性-105DEGC-1000H; %208%%161%%192%%224%%195%%251%%179%%198%: 非固体插装铝电容; CODE: 8010290; DEVICE: UVZ1C221MED1TD
C414 = C: %182%%238%%182%%168%%185%%164%%215%%247%%181%%231%%209%%185%(V): 16; %195%%232%%202%%246%: SMD陶瓷电容-16V-10NF-+/-10%-X7R-0402-BT，TS16949; %208%%161%%192%%224%%195%%251%%179%%198%: SMD陶瓷电容; CODE: 8070449; DEVICE: GRM155R71C103KA01D
C487 = C: %182%%238%%182%%168%%185%%164%%215%%247%%181%%231%%209%%185%(V): 6.3; %195%%232%%202%%246%: SMD陶瓷电容-6.3V-1000NF-+/-10%-X5R-0603; %208%%161%%192%%224%%195%%251%%179%%198%: SMD陶瓷电容; CODE: 8070562; DEVICE: CC0603KRX5R5BB105
C531 C532 = C: %182%%238%%182%%168%%185%%164%%215%%247%%181%%231%%209%%185%(V): 50; %195%%232%%202%%246%: SMD陶瓷电容-50V-0.027NF-+/-5%-NP0-0402-BT; %208%%161%%192%%224%%195%%251%%179%%198%: SMD陶瓷电容; CODE: 8070546; COMPONENT_HIGH_MAX: 0.55MM; DEVICE: C0402C270J5GAC_7867
C534 C538 = C: %182%%238%%182%%168%%185%%164%%215%%247%%181%%231%%209%%185%(V): 50; %195%%232%%202%%246%: SMD陶瓷电容-50V-0.01NF-+/-5%-NP0-0402-BT; %208%%161%%192%%224%%195%%251%%179%%198%: SMD陶瓷电容; CODE: 8070530; COMPONENT_HIGH_MAX: 0.55MM; DEVICE: 04025A100JAT2A
C545 = C: %182%%238%%182%%168%%185%%164%%215%%247%%181%%231%%209%%185%(V): 50; %195%%232%%202%%246%: SMD陶瓷电容-50V-0.1NF-+/-5%-NPO-0402-BT; %208%%161%%192%%224%%195%%251%%179%%198%: SMD陶瓷电容; CODE: 8070450; COMPONENT_HIGH_MAX: 0.55MM; DEVICE: 04025A101JAT2A
D7 D8 D11 D17 = DSBD: %195%%232%%202%%246%: 肖特基二极管-40V-2A-0.5V-SMB-40A; %208%%161%%192%%224%%195%%251%%179%%198%: 肖特基二极管; CODE: 15010198; COMPONENT_HIGH_MAX: 2.44MM; DEVICE: MBRS240LT3
D27 = D_A: %195%%232%%202%%246%: 肖特基二极管-10V-3A-0.24V-SOD323-BT; %208%%161%%192%%224%%195%%251%%179%%198%: 肖特基二极管; CODE: 15010252; COMPONENT_HIGH_MAX: 1.1MM; DEVICE: BAT60BE6327
J16 = JTDA18250
L1 = L: %195%%232%%202%%246%: 贴片电感器-0.0033UH-0.3NH-0.19OHM-0402; %208%%161%%192%%224%%195%%251%%179%%198%: 贴片电感器; CODE: 10031117; COMPONENT_HIGH_MAX: 0.55MM; DEVICE: LL1005_FHL3N3S
L7 = L_E
L9 = SWPA4020S1R0NT
L16 = L: %195%%232%%202%%246%: 贴片电感器-0.0033UH-0.3NH-0.19OHM-0402; %208%%161%%192%%224%%195%%251%%179%%198%: 贴片电感器; CODE: 10031117; COMPONENT_HIGH_MAX: 0.65MM; DEVICE: LL1005_FHL3N3S
L21 = L: %195%%232%%202%%246%: 贴片电感器-4.7UH-20%-0.26OHM-0.43A-20DEGC-2.5*1.8MM-; %208%%161%%192%%224%%195%%251%%179%%198%: 贴片电感器; CODE: 10031116; COMPONENT_HIGH_MAX: 2MM; DEVICE: LQLBC2518T4R7M
LB16 LB19 LB47 = LB: %195%%232%%202%%246%: EMI磁珠-220OHM-0.05OHM-2A-0805; %208%%161%%192%%224%%195%%251%%179%%198%: EMI磁珠; CODE: 10070012; COMPONENT_HIGH_MAX: 1.05MM; DEVICE: MGLB2012_220T_LF
M4-M6 M10 = HOLE-8STARS: %195%%232%%202%%246%: M3螺钉(推荐使用)，对应138MIL星月孔，适用于过波峰焊设计。; DEVICE: 138MIL_STAR_HOLE_APPLY_TO_M3
Q6 = NPN-BEC_0: %195%%232%%202%%246%: 三极管-NPN-40V-200MA-300MW-0.2V-SOT-23-70-BT; %208%%161%%192%%224%%195%%251%%179%%198%: 三极管; COMPONENT_HIGH_MAX: 1.11MM; DEVICE: MMBT3904LT1
R2 = R: %182%%238%%182%%168%%185%%166%%194%%202%(W): 0.1; %195%%232%%202%%246%: 片式厚膜电阻器-0.1W-249OHM-±1%-0603; %208%%161%%192%%224%%195%%251%%179%%198%: 片式厚膜电阻器; %215%%232%%214%%181%%212%%202%%208%%237%%198%%171%%178%%238%: ±1%; CODE: 7090640; COMPONENT_HIGH_MAX: 0.55MM; DEVICE: RHS_03K2490FT
R35 = R: %182%%238%%182%%168%%185%%166%%194%%202%(W): 0.1; %195%%232%%202%%246%: 片式厚膜电阻器-0.1W-150000OHM-+/-1%-0603; %208%%161%%192%%224%%195%%251%%179%%198%: 片式厚膜电阻器; %215%%232%%214%%181%%212%%202%%208%%237%%198%%171%%178%%238%: +/-1%; CODE: 7091239; COMPONENT_HIGH_MAX: 0.55MM; DEVICE: RK73H1JTTD1503F
R51 = R: %182%%238%%182%%168%%185%%166%%194%%202%(W): 0.1; %195%%232%%202%%246%: 片式厚膜电阻器-0.1W-19600OHM-+/-1%-0603; %208%%161%%192%%224%%195%%251%%179%%198%: 片式厚膜电阻器; %215%%232%%214%%181%%212%%202%%208%%237%%198%%171%%178%%238%: +/-1%; CODE: 7090707; COMPONENT_HIGH_MAX: 0.55MM; DEVICE: RC0603FR_0719K6
R60 = R: %182%%238%%182%%168%%185%%166%%194%%202%(W): 0.06; %195%%232%%202%%246%: 片式厚膜电阻器-0.0625W-220OHM-+/-5%-0402-BT; %208%%161%%192%%224%%195%%251%%179%%198%: 片式厚膜电阻器; %215%%232%%214%%181%%212%%202%%208%%237%%198%%171%%178%%238%: +/-5%; CODE: 7090808; COMPONENT_HIGH_MAX: 0.4MM; DEVICE: RC0402JR_07220R
R61-R64 R166 = R: %182%%238%%182%%168%%185%%166%%194%%202%(W): 0.06; %195%%232%%202%%246%: 片式厚膜电阻器-0.0625W-0OHM-< 50MOHM-0402-1A-BT; %208%%161%%192%%224%%195%%251%%179%%198%: 片式厚膜电阻器; %215%%232%%214%%181%%212%%202%%208%%237%%198%%171%%178%%238%: < 50MOHM; CODE: 7090800; DEVICE: RC0402JR_070R
R65 R66 = R: %182%%238%%182%%168%%185%%166%%194%%202%(W): 0.06; %195%%232%%202%%246%: 片式厚膜电阻器-0.0625W-2000OHM-+/-1%-0402; %208%%161%%192%%224%%195%%251%%179%%198%: 片式厚膜电阻器; %215%%232%%214%%181%%212%%202%%208%%237%%198%%171%%178%%238%: +/-1%; CODE: 7091354; COMPONENT_HIGH_MAX: 0.4MM; DEVICE: RC_02W2001FT
R92 = R: %182%%238%%182%%168%%185%%166%%194%%202%(W): 0.06; %195%%232%%202%%246%: 片式厚膜电阻器-0.0625W-10000OHM-+/-1%-0402-BT; %208%%161%%192%%224%%195%%251%%179%%198%: 片式厚膜电阻器; %215%%232%%214%%181%%212%%202%%208%%237%%198%%171%%178%%238%: +/-1%; CODE: 7090867; COMPONENT_HIGH_MAX: 0.4MM; DEVICE: RK73H1ETTP1002F
R112 = R: %182%%238%%182%%168%%185%%166%%194%%202%(W): 0.06; %195%%232%%202%%246%: 片式厚膜电阻器-0.0625W-150OHM-+/-1%-0402--供电专用 07091327-供电专用; %208%%161%%192%%224%%195%%251%%179%%198%: 片式厚膜电阻器; %215%%232%%214%%181%%212%%202%%208%%237%%198%%171%%178%%238%: +/-1%; CODE: 7091730; COMPONENT_HIGH_MAX: 0.4MM; DEVICE: RC0402FR_07150RL
R114 R116 = R: %182%%238%%182%%168%%185%%166%%194%%202%(W): 0.1; %195%%232%%202%%246%: 片式厚膜电阻器-0.1W-2000OHM-+/-5%-0603; %208%%161%%192%%224%%195%%251%%179%%198%: 片式厚膜电阻器; %215%%232%%214%%181%%212%%202%%208%%237%%198%%171%%178%%238%: +/-5%; CODE: 7090643; COMPONENT_HIGH_MAX: 0.55MM; DEVICE: RC0603JR_072K
R117 R121 R123 = R: %182%%238%%182%%168%%185%%166%%194%%202%(W): 0.06; %195%%232%%202%%246%: 片式厚膜电阻器-0.0625W-75000OHM-+/-1%-0402; %208%%161%%192%%224%%195%%251%%179%%198%: 片式厚膜电阻器; %215%%232%%214%%181%%212%%202%%208%%237%%198%%171%%178%%238%: +/-1%; CODE: 7091008; COMPONENT_HIGH_MAX: 0.4MM; DEVICE: RK73H1ETTD7502F
U14 = LM1117-ADJ_0: CODE: 99051CGJ
U17 = MP8126
U34 = AV2012_0
X4 = X3: %195%%232%%202%%246%: 晶体谐振器-27MHZ-20PF-+/-30PPM-40OHM-SMD; %208%%161%%192%%224%%195%%251%%179%%198%: 晶体谐振器; CODE: ?; DEVICE: ESB240000F20D33
C156 = CP_0: %182%%238%%182%%168%%185%%164%%215%%247%%181%%231%%209%%185%(V): 10; %195%%232%%202%%246%: 非固体插装铝电容-10V-100UF-+/-20%-5*11-2-0.5MM-极性-105DEGC-1000H; %208%%161%%192%%224%%195%%251%%179%%198%: 非固体插装铝电容; CODE: 8010158; COMPONENT_HIGH_MAX: 12.5MM; DEVICE: 10YXA100MT15X11
C224 C247 C249 = C: %182%%238%%182%%168%%185%%164%%215%%247%%181%%231%%209%%185%(V): 6.3; %195%%232%%202%%246%: SMD陶瓷电容-6.3V-10000NF-+/-10%-X7R-0805; %208%%161%%192%%224%%195%%251%%179%%198%: SMD陶瓷电容; CODE: 8070693; COMPONENT_HIGH_MAX: 1.45MM; DEVICE: GRM21BR70J106KE76L
C254 C256 C259-C263 C266-C269 C272-C278 = C: %182%%238%%182%%168%%185%%164%%215%%247%%181%%231%%209%%185%(V): 16; %195%%232%%202%%246%: SMD陶瓷电容-16V-100NF-+/-10%-X7R-0402-BT; %208%%161%%192%%224%%195%%251%%179%%198%: SMD陶瓷电容; CODE: 8070614; COMPONENT_HIGH_MAX: 0.55MM; DEVICE: RMEMK105BJ104KV_FR
C292 = C: %182%%238%%182%%168%%185%%164%%215%%247%%181%%231%%209%%185%(V): 10; %195%%232%%202%%246%: SMD陶瓷电容-10V-2200NF-+/-10%-X5R-0603; %208%%161%%192%%224%%195%%251%%179%%198%: SMD陶瓷电容; CODE: 8070573; COMPONENT_HIGH_MAX: 0.9MM; DEVICE: GRM188R61A225KE34D
C311 = C: %182%%238%%182%%168%%185%%164%%215%%247%%181%%231%%209%%185%(V): 10; %195%%232%%202%%246%: SMD陶瓷电容-10V-2200NF-+/-10%-X5R-0805; %208%%161%%192%%224%%195%%251%%179%%198%: SMD陶瓷电容; CODE: 8070418; COMPONENT_HIGH_MAX: 1.45MM; DEVICE: CC0805KKX5R6BB225
C312 = C: %182%%238%%182%%168%%185%%164%%215%%247%%181%%231%%209%%185%(V): 10; %195%%232%%202%%246%: SMD陶瓷电容-10V-2200NF-+/-10%-X5R-0805; %208%%161%%192%%224%%195%%251%%179%%198%: SMD陶瓷电容; CODE: 8070418; COMPONENT_HIGH_MAX: 1.35MM; DEVICE: CC0805KKX5R6BB225
C328 = CP_0: %182%%238%%182%%168%%185%%164%%215%%247%%181%%231%%209%%185%(V): 16; %195%%232%%202%%246%: 非固体插装铝电容-16V-220UF-+/-20%-6.3*11-2.5-0.5MM-极性-105DEGC-1000H; %208%%161%%192%%224%%195%%251%%179%%198%: 非固体插装铝电容; CODE: 8010290; COMPONENT_HIGH_MAX: 12.5MM; DEVICE: UVZ1C221MED1TD
C340 = C: %182%%238%%182%%168%%185%%164%%215%%247%%181%%231%%209%%185%(V): 6.3; %195%%232%%202%%246%: SMD陶瓷电容-6.3V-4700NF-+/-20%-X5R-0603-BT,TS16949; %208%%161%%192%%224%%195%%251%%179%%198%: SMD陶瓷电容; CODE: 8070564; COMPONENT_HIGH_MAX: 0.95MM; DEVICE: CM105X5R475M06AT
R18 = R: %182%%238%%182%%168%%185%%166%%194%%202%(W): 0.1; %195%%232%%202%%246%: 片式厚膜电阻器-0.1W-110OHM-+/-5%-0603; %208%%161%%192%%224%%195%%251%%179%%198%: 片式厚膜电阻器; %215%%232%%214%%181%%212%%202%%208%%237%%198%%171%%178%%238%: +/-5%; CODE: 7090632; COMPONENT_HIGH_MAX: 0.55MM; DEVICE: RK73B1JTTD111J
R47 = R: %182%%238%%182%%168%%185%%166%%194%%202%(W): 0.06; %195%%232%%202%%246%: 片式厚膜电阻器-0.0625W-0OHM-< 50MOHM-0402-1A-BT; %208%%161%%192%%224%%195%%251%%179%%198%: 片式厚膜电阻器; %215%%232%%214%%181%%212%%202%%208%%237%%198%%171%%178%%238%: < 50MOHM; CODE: 7090800; COMPONENT_HIGH_MAX: 0.4MM; DEVICE: RC0402JR_070R
R50 = R: %182%%238%%182%%168%%185%%166%%194%%202%(W): 0.1; %195%%232%%202%%246%: 片式厚膜电阻器-0.1W-249OHM-+/-1%-0603; %208%%161%%192%%224%%195%%251%%179%%198%: 片式厚膜电阻器; %215%%232%%214%%181%%212%%202%%208%%237%%198%%171%%178%%238%: +/-1%; CODE: 7090640; COMPONENT_HIGH_MAX: 0.55MM; DEVICE: RHS_03K2490FT
R79 = R: %182%%238%%182%%168%%185%%166%%194%%202%(W): 0.1; %195%%232%%202%%246%: 片式厚膜电阻器-0.1W-82500OHM-+/-1%-0603; %208%%161%%192%%224%%195%%251%%179%%198%: 片式厚膜电阻器; %215%%232%%214%%181%%212%%202%%208%%237%%198%%171%%178%%238%: +/-1%; CODE: 7090737; COMPONENT_HIGH_MAX: 0.55MM; DEVICE: RC0603FR_0782K5
R197 = R: %182%%238%%182%%168%%185%%166%%194%%202%(W): 0.1; %195%%232%%202%%246%: 片式厚膜电阻器-0.1W-220000OHM-+/-1%-0603; %208%%161%%192%%224%%195%%251%%179%%198%: 片式厚膜电阻器; %215%%232%%214%%181%%212%%202%%208%%237%%198%%171%%178%%238%: +/-1%; CODE: 7091009; COMPONENT_HIGH_MAX: 0.55MM; DEVICE: RC0603FR_07220KL
R198 = R: %195%%232%%202%%246%: 片式厚膜电阻器-0.1W-4700OHM-±5%-0603; CODE: 7090246; COMPONENT_HIGH_MAX: 0.55MM; DEVICE: RC0603JR_074K7
R199 = R: %182%%238%%182%%168%%185%%166%%194%%202%(W): 0.1; %195%%232%%202%%246%: 片式厚膜电阻器-0.1W-4700OHM-+/-5%-0603-TS16949; %208%%161%%192%%224%%195%%251%%179%%198%: 片式厚膜电阻器; %215%%232%%214%%181%%212%%202%%208%%237%%198%%171%%178%%238%: +/-5%; CODE: 7090246; COMPONENT_HIGH_MAX: 0.6MM; DEVICE: RC0603JR_074K7
R201 R204 = R: %182%%238%%182%%168%%185%%166%%194%%202%(W): 0.06; %195%%232%%202%%246%: 片式厚膜电阻器-0.0625W-22OHM-+/-5%-0402-BT; %208%%161%%192%%224%%195%%251%%179%%198%: 片式厚膜电阻器; %215%%232%%214%%181%%212%%202%%208%%237%%198%%171%%178%%238%: +/-5%; CODE: 7090803; COMPONENT_HIGH_MAX: 0.4MM; DEVICE: RC0402JR_0722RL
R216 = R: %182%%238%%182%%168%%185%%166%%194%%202%(W): 0.1; %195%%232%%202%%246%: 片式厚膜电阻器-0.1W-1000OHM-+/-5%-0603-TS16949; %208%%161%%192%%224%%195%%251%%179%%198%: 片式厚膜电阻器; %215%%232%%214%%181%%212%%202%%208%%237%%198%%171%%178%%238%: +/-5%; CODE: 7090277; COMPONENT_HIGH_MAX: 0.6MM; DEVICE: RC0603JR_071K
U18 = ETA5050_1: DEVICE: ETA5050S2F
U21 = TLV1117CKTPR: %195%%232%%202%%246%: SWITCHING REGULATORS-3V~12V-0.2%-1A-SOT223-SMT-终端专用-终端专用-00478074; CODE: 39110641; COMPONENT_HIGH_MAX: 0; DEVICE: AZ1117H_ADJTRG1
U25 = HI3137V100

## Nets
1V1_ADC_T: C275.1(A) C309.1(A) LB23.2 U25.28(AVDD11_PLL) U25.33(AVDD11_ADC)
1V1_AVDDREF: C254.1(A) R201.2(B) U25.31(AVDDREF)
1V1_VDD_T: C256.1(A) C273.1(A) C274.1(A) C276.1(A) C277.1(A) R223.2(B) U25.1(VDD1) U25.12(VDD2) U25.18(VDD3) U25.21(VDD4) U25.27(VDD5) U25.37(VDD6) U25.44(VDD7)
1V2_ADC_S: C125.1(A) C209.1(A) LB13.2 U2.33(ADC_VDD12)
1V2_APLL_S: C126.1(A) C210.1(A) LB15.2 U2.28(AVDD12_PLL)
1V2_DVDD_S: C109.1(A) C110.1(A) C113.1(A) C117.1(A) C205.1(A) LB10.2 U2.7(DVDD12_1) U2.17(DVDD12_2) U2.25(DVDD12_3) U2.42(DVDD12_4)
1V8_T: C247.1(A) C278.1(A) R50.2(B) U21.2(OUT1) U21.4(OUT2) ; also on sheet 8
3V3_AVDD_S: C86.1(A) C201.1(A) LB6.2 R69.1(A) U2.30(AVDD33_PLL)
3V3_AVDD_T: C263.1(A) C311.1(A) R216.1(A) R221.2(B) U25.30(AVDD33_PLL)
3V3_DVDD_S: C73.1(A) C74.1(A) C75.1(A) C81.1(A) C200.1(A) LB1.2 R35.1(A) R65.1(A) R66.1(A) R103.2(B) R104.1(A) R108.1(A) R116.2(B) U2.4(DVDD33_1) U2.11(DVDD33_2) U2.19(DVDD33_3) U2.45(DVDD33_4)
3V3_DVDD_T: C156.1 C261.1(A) C262.1(A) C269.1(A) C272.1(A) LB19.2 R206.1(A) R207.1(A) U25.7(DVDD33_1) U25.17(DVDD33_2) U25.20(DVDD33_3) U25.25(DVDD33_4) U25.41(DVDD33_5) U25.45(DVDD33_6)
3V3_MOS_S: C7.1(A) C87.1(A) C88.1(A) J3.5(A5) L21.1(A) LB1.1 LB6.1
3V3_MOS_T: C249.1(A) C265.1(A) C292.1(A) C312.1(A) C349.1(A) J4.5(A5) LB16.1 LB19.1 R221.1(A) U18.1(VDD) U18.3(CE) U21.3(INPUT)
3V3_RF: C57.1(A) C144.1(A) C169.2(B) C195.2(B) C296.1 L21.2(B) R112.2(B) U14.2(VOUT1) U14.4(VOUT2) U34.23(VCCREG1) U34.28(VCCREG2)
3V3_TUNER: C259.1(A) C260.1(A) C328.1 LB16.2 ; also on sheet 8
5V0_MOS_S: C8.1(A) C92.1(A) C202.1(A) J3.3(A3) LB47.1 U12.3(VIN)
5V0_MOS_T: C352.1(A) J4.3(A3) ; also on sheet 8
12V0_MOS_S: C9.1(A) C136.1(A) C183.1(A) J3.1(A1) L7.1 R117.1(A) R121.1(A) U17.3(VDD)
GND: C1.2(B) C7.2(B) C8.2(B) C9.2(B) C37.2(B) C38.2(B) C57.2(B) C58.2(B) C73.2(B) C74.2(B) C75.2(B) C78.2(B) C81.2(B) C86.2(B) C87.2(B) C88.2(B) C92.2(B) C103.2(B) C104.2(B) C105.2(B) C109.2(B) C110.2(B) C113.2(B) C117.2(B) C125.2(B) C126.2(B) C130.2(B) C131.2(B) C134.2 C136.2(B) C144.2(B) C145.2(B) C148.2(B) C151.2(B) C156.2 C163.1(A) C166.2(B) C167.2 C168.1(A) C169.1(A) C170.2(B) C171.1(A) C172.2(B) C174.2(B) C176.2(B) C183.2(B) C190.2(B) C194.2(B) C195.1(A) C200.2(B) C201.2(B) C202.2(B) C204.2(B) C205.2(B) C209.2(B) C210.2(B) C217.2(B) C221.2(B) C224.2(B) C225.1(A) C226.2(B) C241.2(B) C244.2(B) C246.2(B) C247.2(B) C249.2(B) C254.2(B) C256.2(B) C259.2(B) C260.2(B) C261.2(B) C262.2(B) C263.2(B) C265.2(B) C268.2(B) C269.2(B) C272.2(B) C273.2(B) C274.2(B) C275.2(B) C276.2(B) C277.2(B) C278.2(B) C287.2(B) C288.2(B) C292.2(B) C295.2(B) C296.2 C298.2(B) C299.2(B) C300.2(B) C304.1(A) C305.1(A) C309.2(B) C311.2(B) C312.2(B) C322.1(A) C325.1(A) C328.2 C340.2(B) C349.2(B) C352.2(B) C414.2(B) C487.1(A) C531.2(B) C532.2(B) C534.2(B) C535.2(B) C536.2(B) C537.2(B) C538.2(B) C545.2(B) D11.1(A) J3.2(A2) J3.4(A4) J3.6(A6) J3.7(A7) J3.8(A8) J3.18(A18) J3.20(A20) J4.2(A2) J4.4(A4) J4.6(A6) J4.7(A7) J4.8(A8) J4.18(A18) J4.20(A20) J5.1(A1) J5.2(A2) J5.3(A3) J5.4(A4) J15.1(A1) J15.2(A2) J15.3(A3) J15.4(A4) J16.3(GND1) J16.4(GND2) J16.5(GND3) J16.6(GND4) J16.7(GND5) J16.8(GND6) L16.1(A) M4.1(GND0) M4.2(GND1) M4.3(GND2) M4.4(GND3) M4.5(GND4) M4.6(GND5) M4.7(GND6) M4.8(GND7) M5.1(GND0) M5.2(GND1) M5.3(GND2) M5.4(GND3) M5.5(GND4) M5.6(GND5) M5.7(GND6) M5.8(GND7) M6.1(GND0) M6.2(GND1) M6.3(GND2) M6.4(GND3) M6.5(GND4) M6.6(GND5) M6.7(GND6) M6.8(GND7) M10.1(GND0) M10.2(GND1) M10.3(GND2) M10.4(GND3) M10.5(GND4) M10.6(GND5) M10.7(GND6) M10.8(GND7) Q6.2(E) R2.2(B) R4.2(B) R18.2(B) R41.2(B) R59.2(B) R64.2(B) R72.2(B) R83.2(B) R92.2(B) R102.1(A) R123.2(B) R141.2(B) R197.2(B) R198.2(B) R204.2(B) R205.2(B) R208.2(B) R209.2(B) U2.29(PLL_GND) U2.34(ADC_GND) U2.47(GND) U2.49(SINK) U17.1(SGND) U17.16(PGND) U17.17(SINK) U18.2(GND) U25.29(AVSS_PLL) U25.34(AVSS_ADC) U25.49(SINK) U34.29(EPAD) ; also on sheet 6 7 8
VINNQ: C267.1(A) C299.1(A) U25.36(VINNQ)
VINPQ: C266.1(A) C300.1(A) U25.35(VINPQ)
3136_ADDR0: R41.1(A) U2.39(ADDR0)
3136_ADDR1: R103.1(A) U2.38(ADDR1)
3136_DISEQC_IN: Q6.3(C) R51.1(A) R116.1(A) U2.13(DISEQC_IN)
3136_DISEQC_OUT: R123.1(A) U2.12(DISEQC_OUT) U17.9(EXTM)
3136_FUNC_SEL: R4.1(A) U2.14(FUNC_SEL)
3136_HV_SEL: U2.18(HV_SEL) U17.8(13V/18V)
3136_I2C_SCL: C221.1(A) J3.23(A23) R108.2(B) U2.41(SCL)
3136_I2C_SDA: C217.1(A) J3.24(A24) R104.2(B) U2.40(SDA)
3136_IOUT_N: C307.2(B) U2.32(VINNI)
3136_IOUT_P: C303.2(B) U2.31(VINPI)
3136_LNB_EN: U2.21(LNB_EN) U17.5(EN)
3136_QOUT_N: C186.2(B) U2.35(VINNQ)
3136_QOUT_P: C306.2(B) U2.36(VINPQ)
3136_RF_AGC: C37.1(A) R60.1(A) R127.2(B)
3136_RSTN: C38.1(A) J3.10(A10) R83.1(A) U2.15(RSTN)
3136_TS_CLK: R10.2(B) U2.46(TS_CLK)
3136_TS_OUT0: R13.2(B) U2.48(TS_OUT0)
3136_TS_OUT1: R12.2(B) U2.1(TS_OUT1)
3136_TS_OUT2: R14.2(B) U2.2(TS_OUT2)
3136_TS_OUT3: R16.2(B) U2.3(TS_OUT3)
3136_TS_OUT4: R19.2(B) U2.5(TS_OUT4)
3136_TS_OUT5: R20.2(B) U2.6(TS_OUT5)
3136_TS_OUT6: R21.2(B) U2.8(TS_OUT6)
3136_TS_OUT7: R25.2(B) U2.9(TS_OUT7)
3136_TS_SYNC: R226.2(B) U2.43(TS_SYNC)
3136_TS_VAL: C176.1(A) R5.2(B) U2.44(TS_VALID)
3136_TSI_CLK: J3.19(A19) R10.1(A)
3136_TSI_D0: J3.17(A17) R13.1(A)
3136_TSI_D1: J3.15(A15) R12.1(A)
3136_TSI_D2: J3.16(A16) R14.1(A)
3136_TSI_D3: J3.13(A13) R16.1(A)
3136_TSI_D4: J3.14(A14) R19.1(A)
3136_TSI_D5: J3.11(A11) R20.1(A)
3136_TSI_D6: J3.12(A12) R21.1(A)
3136_TSI_D7: J3.9(A9) R25.1(A)
3136_TSI_SYNC: J3.22(A22) R226.1(A)
3136_TSI_VALID: J3.21(A21) R5.1(A)
3136_XIN: C172.1(A) R24.1(A) U2.23(XIN) X6.2
3136_XOUT: C174.1(A) R24.2(B) U2.22(XOUT) X6.1
3137_ADDR0: R209.1(A) U25.40(ADDR0)
3137_ADDR1: R208.1(A) U25.38(ADDR1)
3137_FUNC_SEL: R205.1(A) U25.14(FUNC_SEL)
3137_I2C_SCL: J4.23(A23) R81.1(A) R206.2(B)
3137_I2C_SDA: J4.24(A24) R80.1(A) R207.2(B)
3137_IF_AGC: C268.1(A) R199.2(B) ; also on sheet 8
3137_RSTN: C340.1(A) J4.10(A10) R198.1(A) U25.15(RSTN)
3137_TSI_CLK: J4.19(A19) R133.1(A)
3137_TSI_D0: J4.17(A17) R134.1(A)
3137_TSI_D1: J4.15(A15) R165.1(A)
3137_TSI_D2: J4.16(A16) R227.1(A)
3137_TSI_D3: J4.13(A13) R228.1(A)
3137_TSI_D4: J4.14(A14) R230.1(A)
3137_TSI_D5: J4.11(A11) R231.1(A)
3137_TSI_D6: J4.12(A12) R232.1(A)
3137_TSI_D7: J4.9(A9) R233.1(A)
3137_TSI_SYNC: J4.22(A22) R128.1(A)
3137_TSI_VALID: J4.21(A21) R132.1(A)
3137_XIN: C325.2(B) R47.1(A) R164.2(B) U25.23(XIN) X3.2
3137_XOUT: C322.2(B) R164.1(A) U25.22(XOUT) X3.1
AC2012_SCL_T: R61.2(B) R65.2(B) U2.27(SCLT)
AC2012_SDA_T: R62.2(B) R66.2(B) U2.26(SDAT)
ANT_CTRL/LOCK: U25.16(LOCK) ; also on sheet 8
CLK_TU_OUT: R47.2(B) ; also on sheet 8
IF_OUTN: C266.2(B) ; also on sheet 8
IF_OUTP: C267.2(B) ; also on sheet 8
LNB_PWR: C58.1(A) C64.1(A) C78.1(A) C104.1(A) C155.2(B) C170.1(A) D17.2(B) D27.1(K) J16.2(ANT_IN)
LNB_PWR_B: C166.1(A) C287.1(A) C288.1(A) D27.2(A) R166.2(B)
LOOPTHROUGH: C283.1(A) J16.1(LOOP) R166.1(A)
MXL603_SCL: U25.26(SCLT) ; also on sheet 8
MXL603_SDA: U25.24(SDAT) ; also on sheet 8
REG2OUT: C130.1(A) C131.1(A) C225.2(B) C414.1(A) U34.1(REG2OUT) U34.2(VCCRF1) U34.5(VCCRF2) U34.10(VCCZIF) U34.25(VCCCP)
RESET_TUNER: U25.19(CLK_OUT) ; also on sheet 8
N07307: R230.2(B) U25.6(TS_DATA4)
N07315: R231.2(B) U25.8(TS_DATA5)
N07323: R227.2(B) U25.4(TS_DATA2)
N07331: R165.2(B) U25.3(TS_DATA1)
N07339: R134.2(B) U25.2(TS_DATA0)
N07347: R132.2(B) U25.47(TS_VALID)
N07357: R128.2(B) U25.46(TS_SYNC)
N07635: C295.1(A) R80.2(B) U25.42(SDA)
N07717: R201.1(A) R222.2(B)
N07721: C224.1(A) C345.1(A) LB23.1 R79.1(A) R222.1(A) R223.1(A) U18.5(VOUT)
N07749: C345.2(B) R79.2(B) R197.1(A) U18.4(FB)
N07781: R204.1(A) U25.32(AGNDREF)
N07785: C298.1(A) R81.2(B) U25.43(SCL)
N07803: R133.2(B) U25.48(TS_CLK)
N07829: R199.1(A) R216.2(B) U25.39(AGC)
N07925: R18.1(A) R50.1(A) U21.1(ADJ/GND)
N07935: R228.2(B) U25.5(TS_DATA3)
N07943: R232.2(B) U25.9(TS_DATA6)
N07951: R233.2(B) U25.10(TS_DATA7)
N10370: C1.1(A) C139.2(B) D8.2(B) L9.2(B) U17.13(VBOOST)
N10408: D7.1(A) L7.2 U17.15(SW)
N10424: C163.2(B) C175.2(B) U17.4(COMP)
N10486: C303.1(A) C537.1(A) U34.12(RXIP)
N10496: C241.1(A) C307.1(A) U34.11(RXIN)
N10506: C186.1(A) C535.1(A) U34.9(RXQN)
N10514: C306.1(A) C536.1(A) U34.8(RXQP)
N10522: R64.1(A) U34.13(PD)
N10528: R59.1(A) U34.14(ADDR0)
N10534: C538.1(A) R61.1(A) U34.15(SCL)
N10544: C534.1(A) R62.1(A) U34.16(SDA)
N10556: C531.1(A) U34.19(XTAL1) X4.2
N10568: C532.1(A) U34.18(XTAL2) X4.1
N10576: C190.1(A) C194.1(A) U34.20(VCCXO) U34.21(VDDD) U34.22(REG1OUT)
N10644: C168.2(B) U34.24(CP)
N10652: C487.2(B) U34.26(REGCAP2) U34.27(REGCAP1)
N10678: C282.1(A) C283.2(B) L16.2(B)
N10686: C282.2(B) U34.7(RFLP)
N10694: L1.2(B) R63.1(A) U34.3(RFIN+)
N10702: C545.1(A) R60.2(B) U34.6(RFAGC)
N10712: C148.1(A) U34.4(RFIN-)
N10716: C304.2(B) R63.2(B)
N10724: C64.2(B) C305.2(B) L1.1(A)
N10736: R2.1(A) R112.1(A) U14.1(ADJ)
N10744: C105.1(A) C145.1(A) LB47.2 U14.3(VIN)
N10756: C171.2(B) U17.2(BYPASS)
N10760: C175.1(A) R102.2(B)
N10764: R117.2(B) U17.6(LINEDROP)
N10768: R121.2(B) U17.7(POK)
N10772: C139.1(A) U17.14(BST)
N10776: C134.1 D7.2(B) L9.1(A)
N10784: C151.1(A) C167.1 C244.1(A) D8.1(A) D11.2(B) D17.1(A) U17.12(VOUT)
N10808: R92.1(A) U17.11(ILIMIT)
N10812: C246.1(A) U17.10(TCAP)
N10816: Q6.1(B) R51.2(B) R114.1(A)
N10824: C155.1(A) R35.2(B) R114.2(B)
N12976: C226.1(A) U2.24(CLK_OUT)
N12982: R68.1(A) R141.1(A) U12.1(ADJ)
N12990: C103.1(A) C204.1(A) LB10.1 LB13.1 LB15.1 R68.2(B) U12.2(VOUT1) U12.4(VOUT2)
N13070: R69.2(B) R127.1(A) U2.37(AGC)
N38177: R72.1(A) U34.17(ADDR1)

Not connected (* = marked no-connect by the designer): ID1 1; ID2 1; ID3 1; ID4 1; ID5 1; ID6 1; J4 1(A1); M4 9(HOLE); M5 9(HOLE); M6 9(HOLE); M10 9(HOLE); U2 10(TS_ERR) 16(FSK_OUT) 20(FSK_IN); U25 11(TS_ERR) 13(FEC_ERR)

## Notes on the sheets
sheet 1
- Hi313XSUB
- PAGE1
- Title Page
- PAGE2
- Block Diagram
- PAGE3
- Hi3136V100
- VER_A
- PAGE4
- AV2012
- PAGE5
- Hi3137V100
- PAGE6
- MXL603//MXL608
- PAGE7
- Hi3130V200
- Hi3130//Hi3136//Hi3137 Sub Board
- PAGE8
- TDA18250B
sheet 2
- Hi3130+TDA18250B
- Hi3136+AV2012
- Hi3137+MXL603
sheet 3
- Hi3136V100
- 3136 I2C ADDR RD: 0xB5
- WR: 0xB4
- PKG_TYPE=MLF48B-040-0606L
- CLose to U2
sheet 4
- DVB-S2 Tuner&LNB Power
- length
- Track1
- 900mil(Point A to Point B)
- Track2
- 350mil(Point B to Point C)
- 75ohm
- A
- 75ohm
- 75ohm
- VO=1.25x(1+249/150)=3.325V
- Track1:90ohm
- B
- Track2:90ohm
- C
- 75ohm
- D
- 75ohm
- 75ohm
- 75ohm
- Track4:90ohm
- 1%
- E
- F
- 1%
- Track3:90ohm
- length
- Track3
- 900mil(Point D to Point E)
- Track4
- 350mil(Point E to Point F)
- C
- B
- E
- HV_SEL
- 1
- 19V
- 0
- 14V
sheet 5
- HI3137V100
- I2C address is 0xB8
- Z0=22ohm
- VOUT=0.8(1+R16/R19)
- Fs=+-30ppm
- Ft=+-30ppm
- CL=20pF
- 1V8 LDO
- VOUT=1.25(1+R8/R3)
- The trace impedance
- Z0=22ohm
- IIC Write Address
  select：
- IIC Addr
- 0xB8
- 0xBA
- 0xBC
- 0xBE
- ADDR0
- 0
- 1
- 0
- 1
- 1
- ADDR1
- 0
- 0
- 1
- 1."0" low level ;"1" high level
- 2.Hi3137 Current address is 0xB8
